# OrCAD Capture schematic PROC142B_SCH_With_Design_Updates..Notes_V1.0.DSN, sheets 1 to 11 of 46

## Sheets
1 17. SOC POWER SUPPLIES-DECAPS 2: size C; title: SOC POWER SUPPLIES - DECAPS 2; rev: B
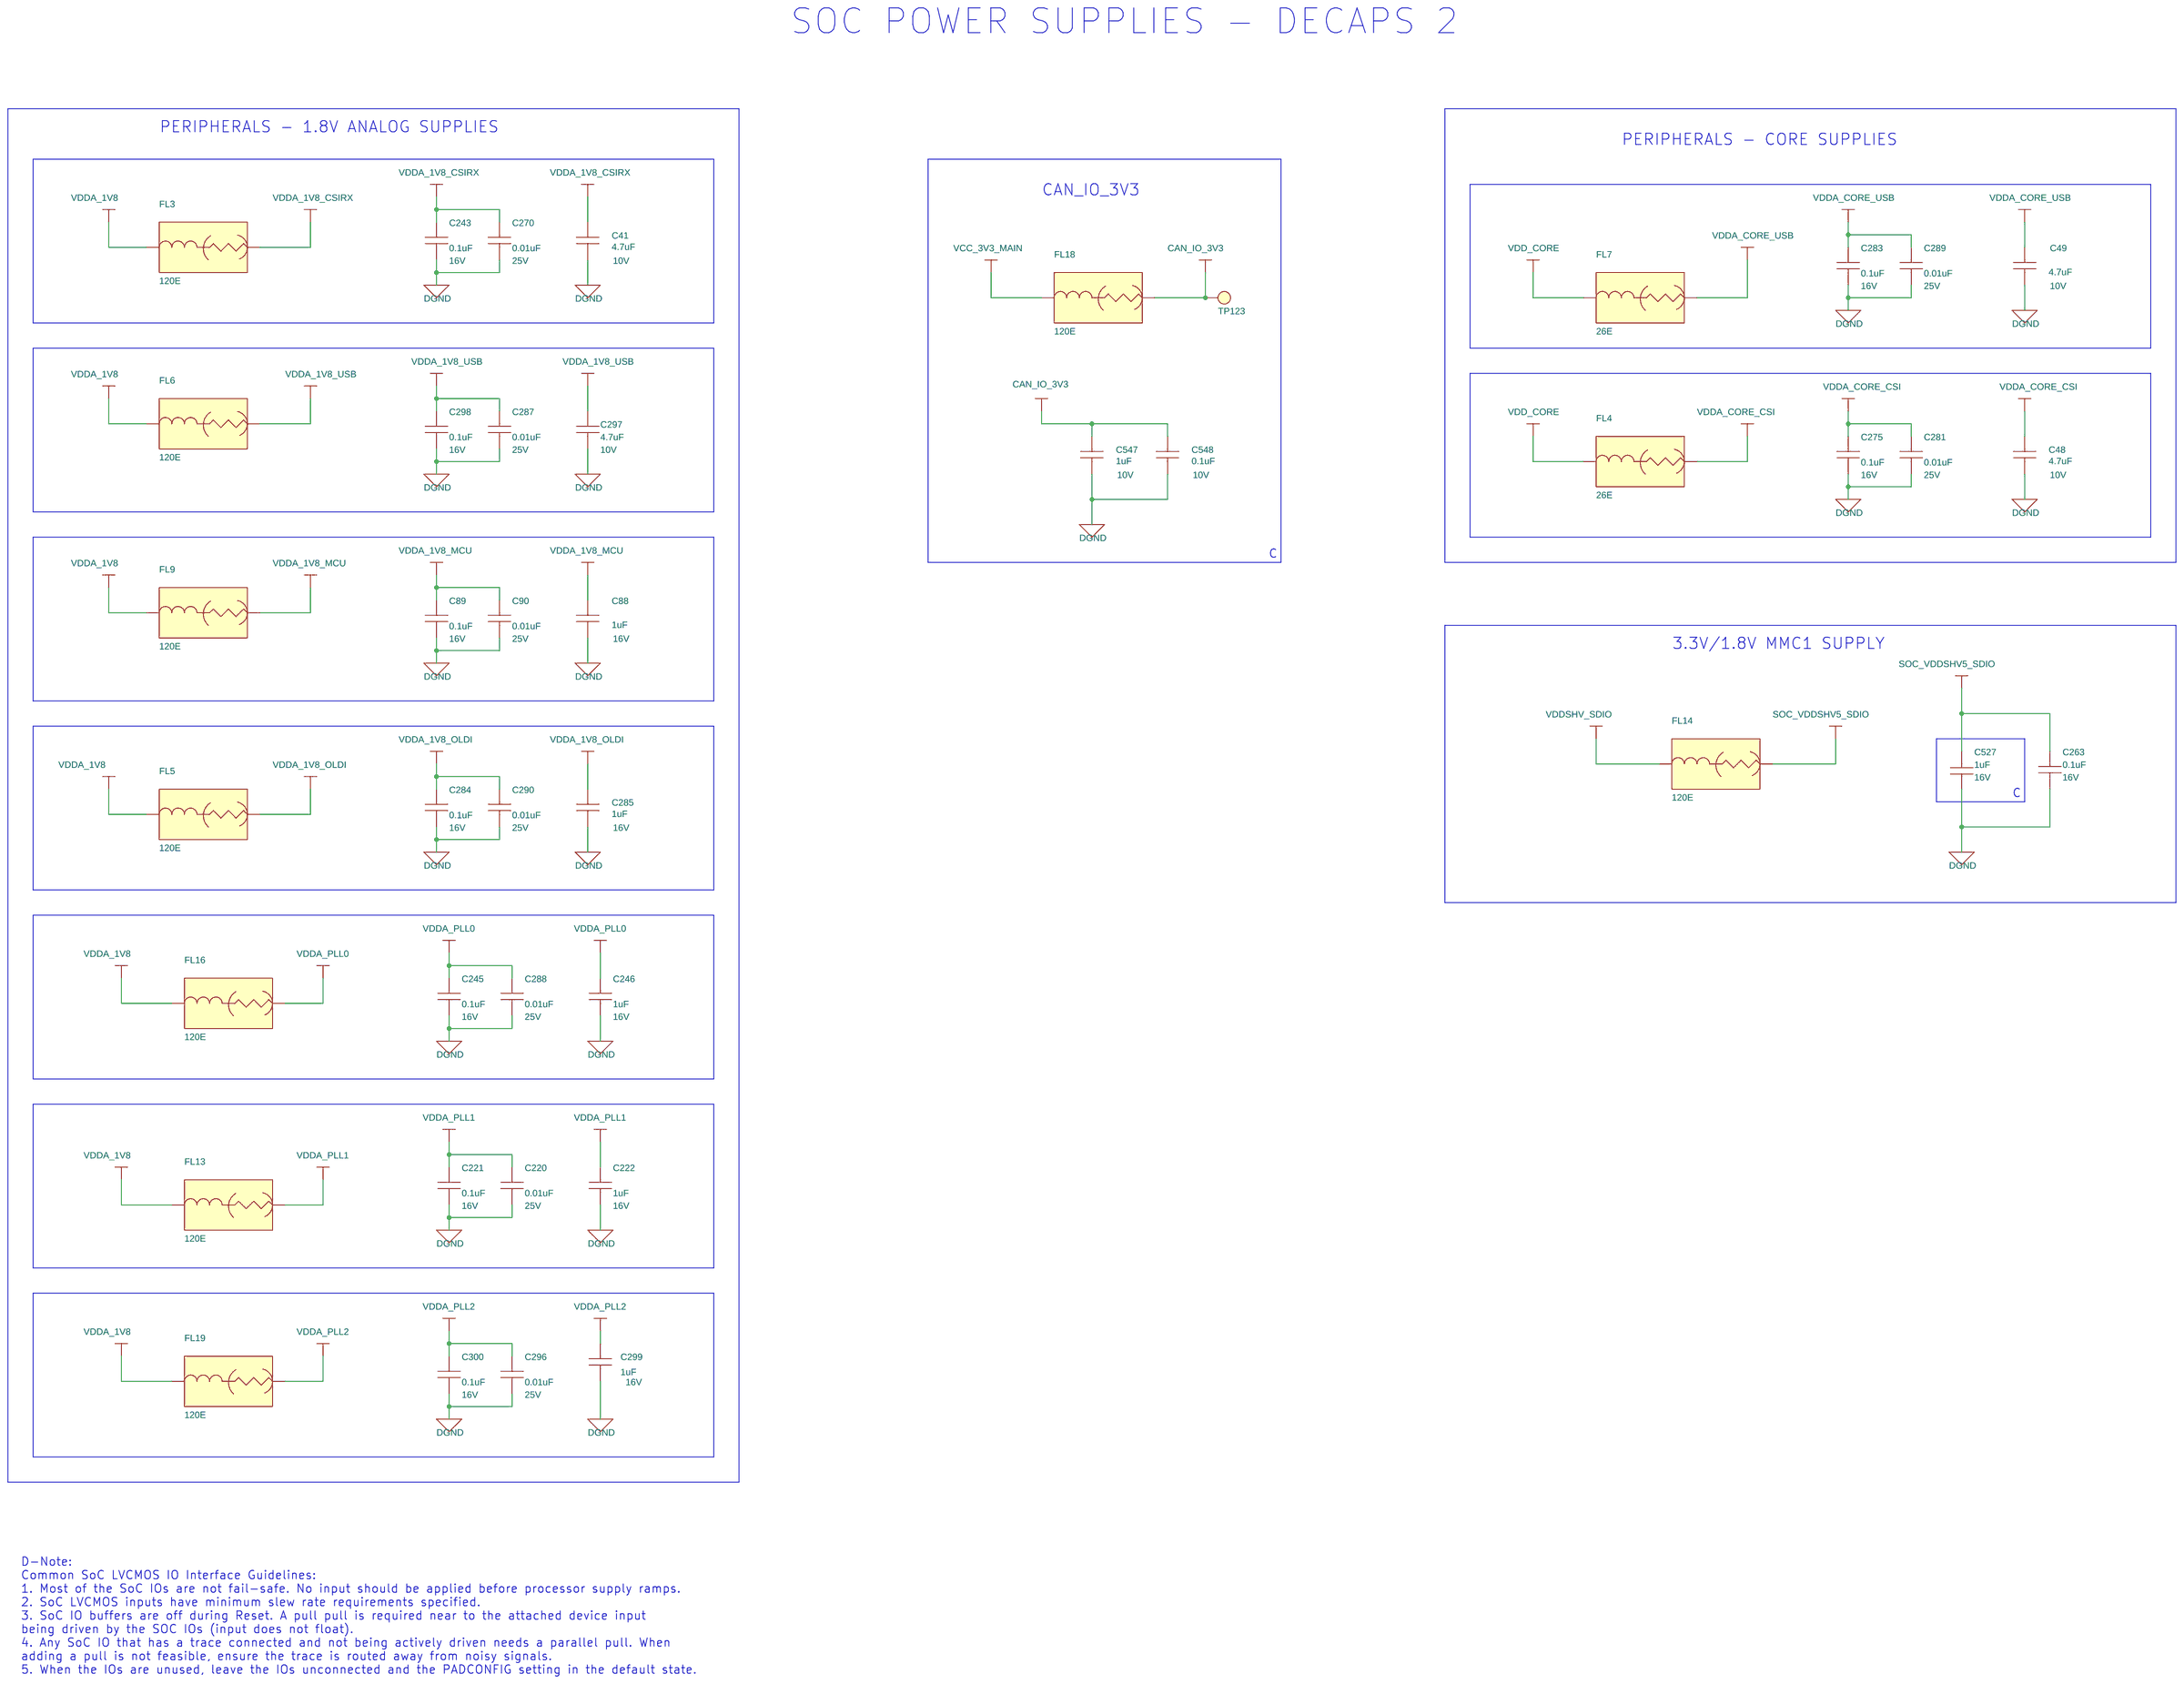
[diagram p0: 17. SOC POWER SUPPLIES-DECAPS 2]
2 03. LINKS TO KEY COLLATERAL&FAQ: title: LINKS TO KEY COLLATERALS AND FAQs
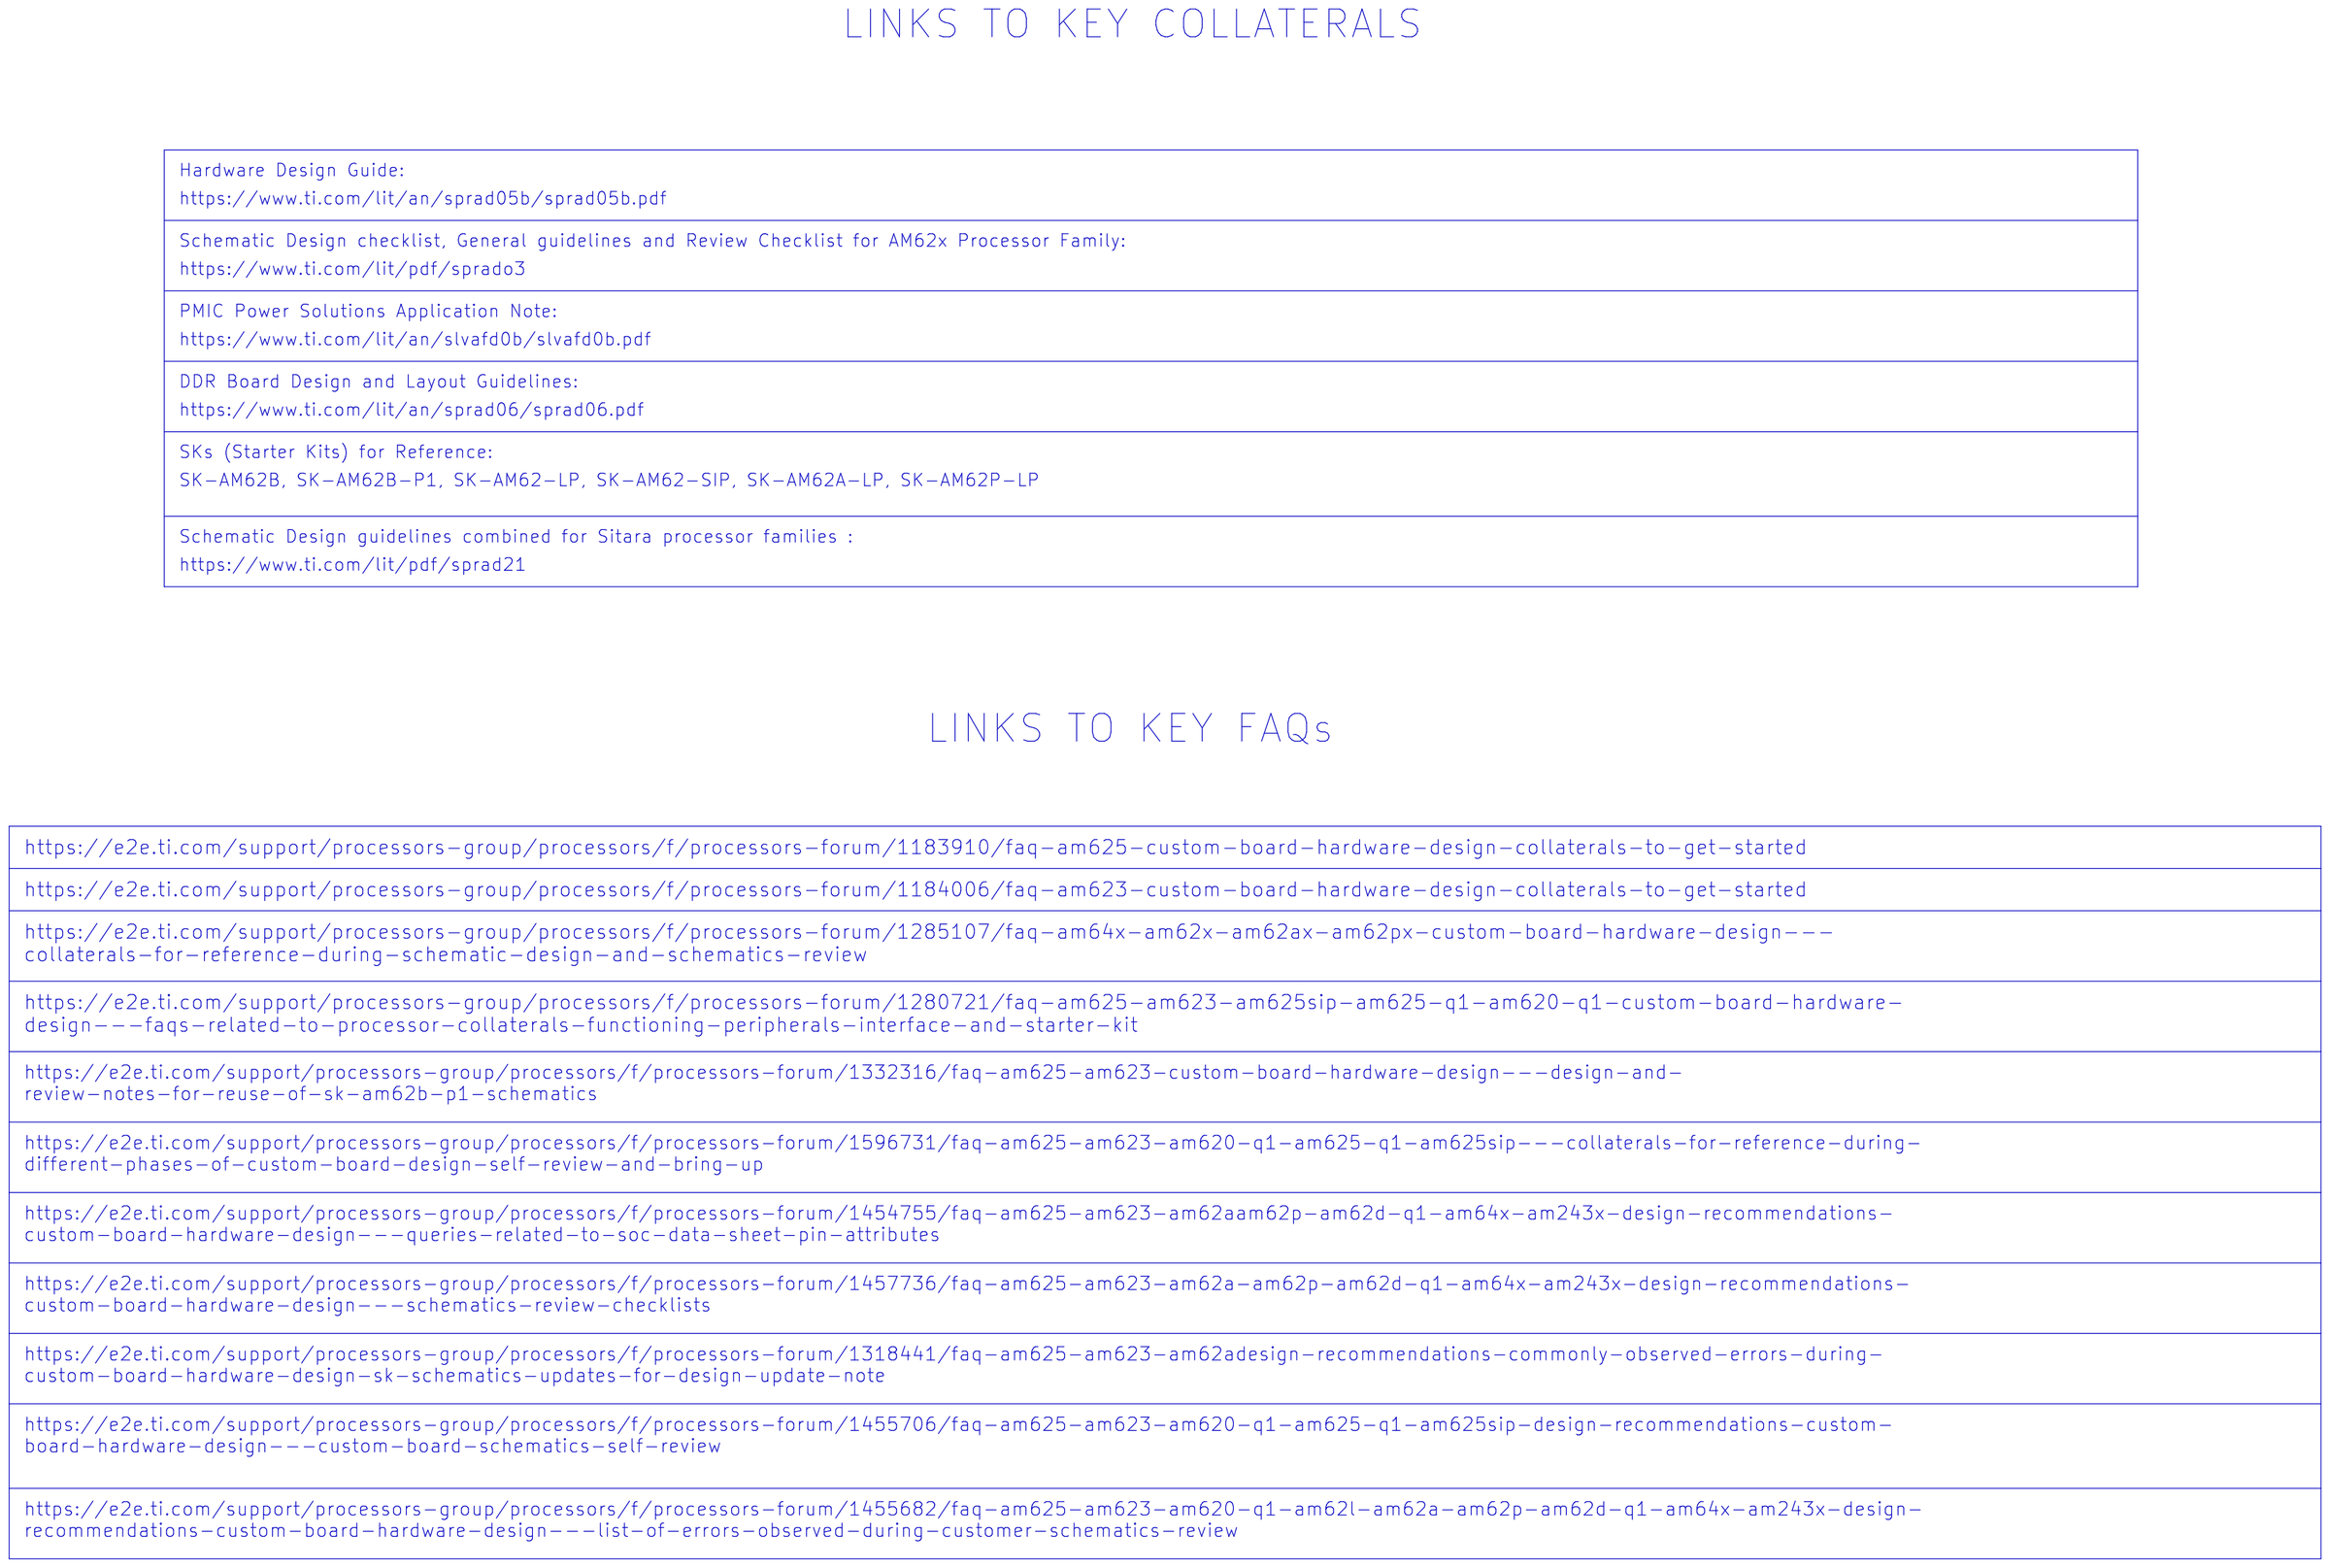
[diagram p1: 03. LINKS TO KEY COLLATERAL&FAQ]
3 30. AUTOMATION SIGNALS BUFFER: size C; title: AUTOMATION SIGNALS BUFFER
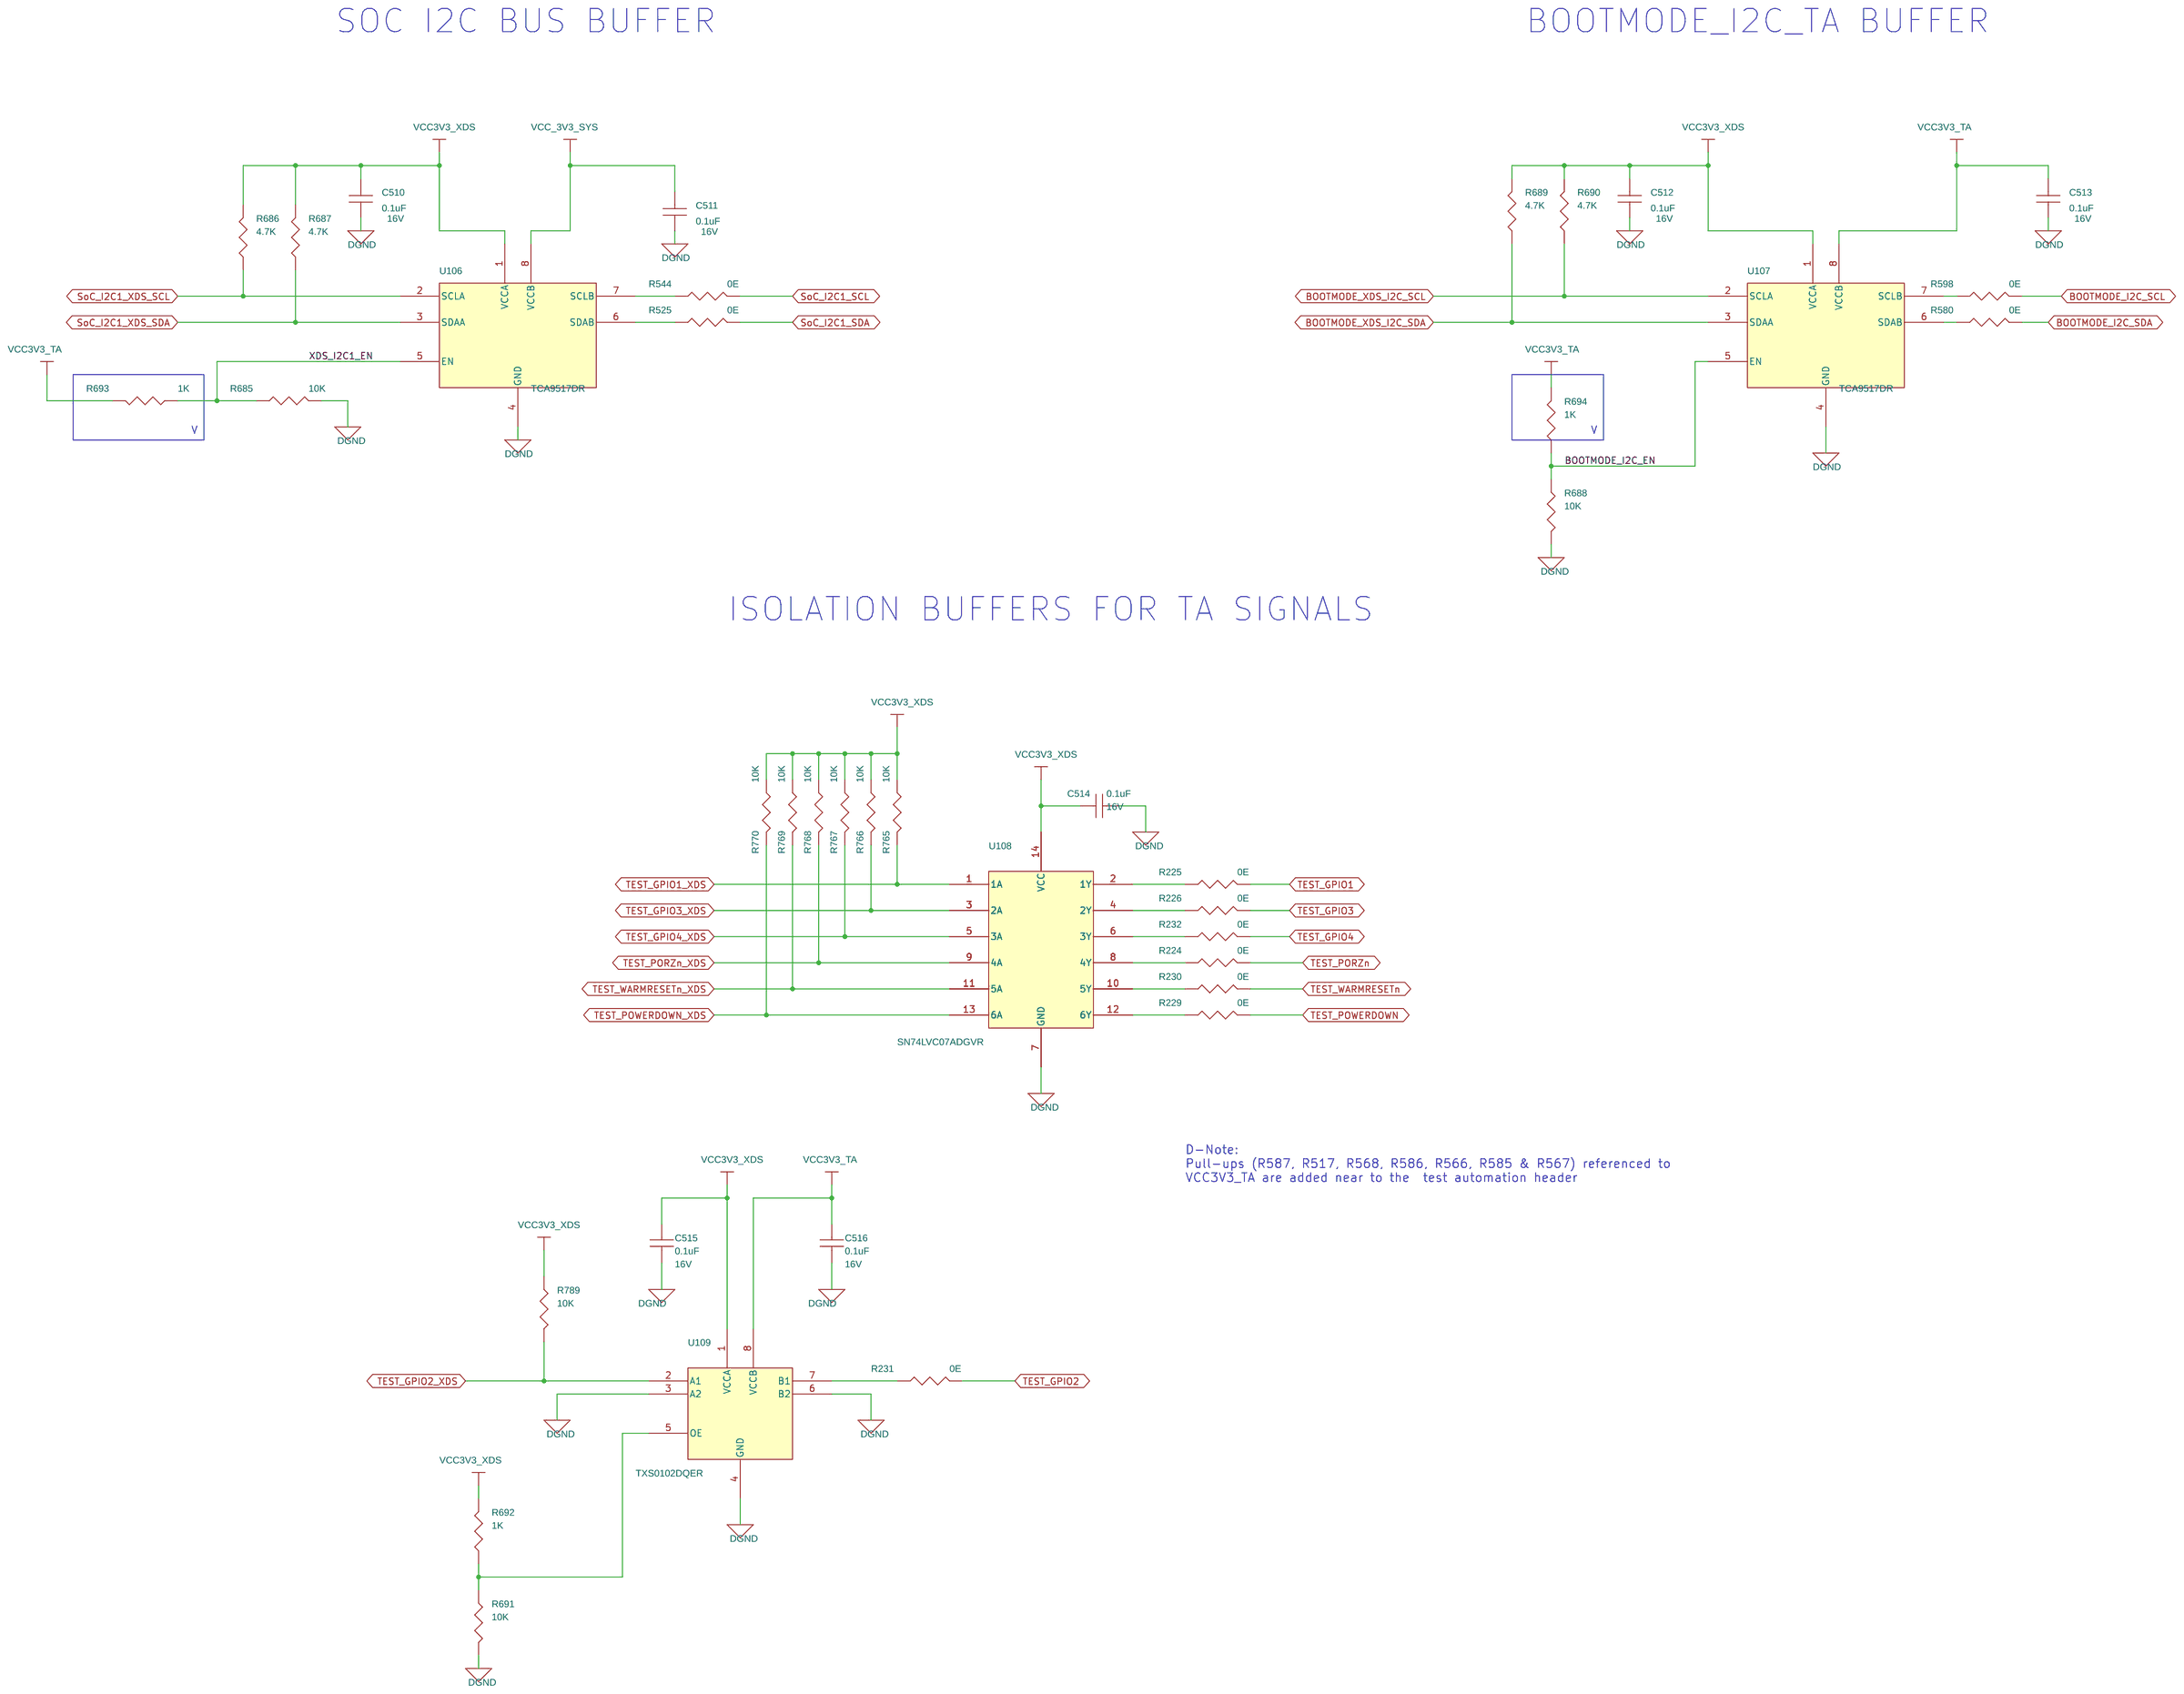
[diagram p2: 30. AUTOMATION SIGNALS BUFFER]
4 01. TABLE OF CONTENTS: title: TABLE OF CONTENTS
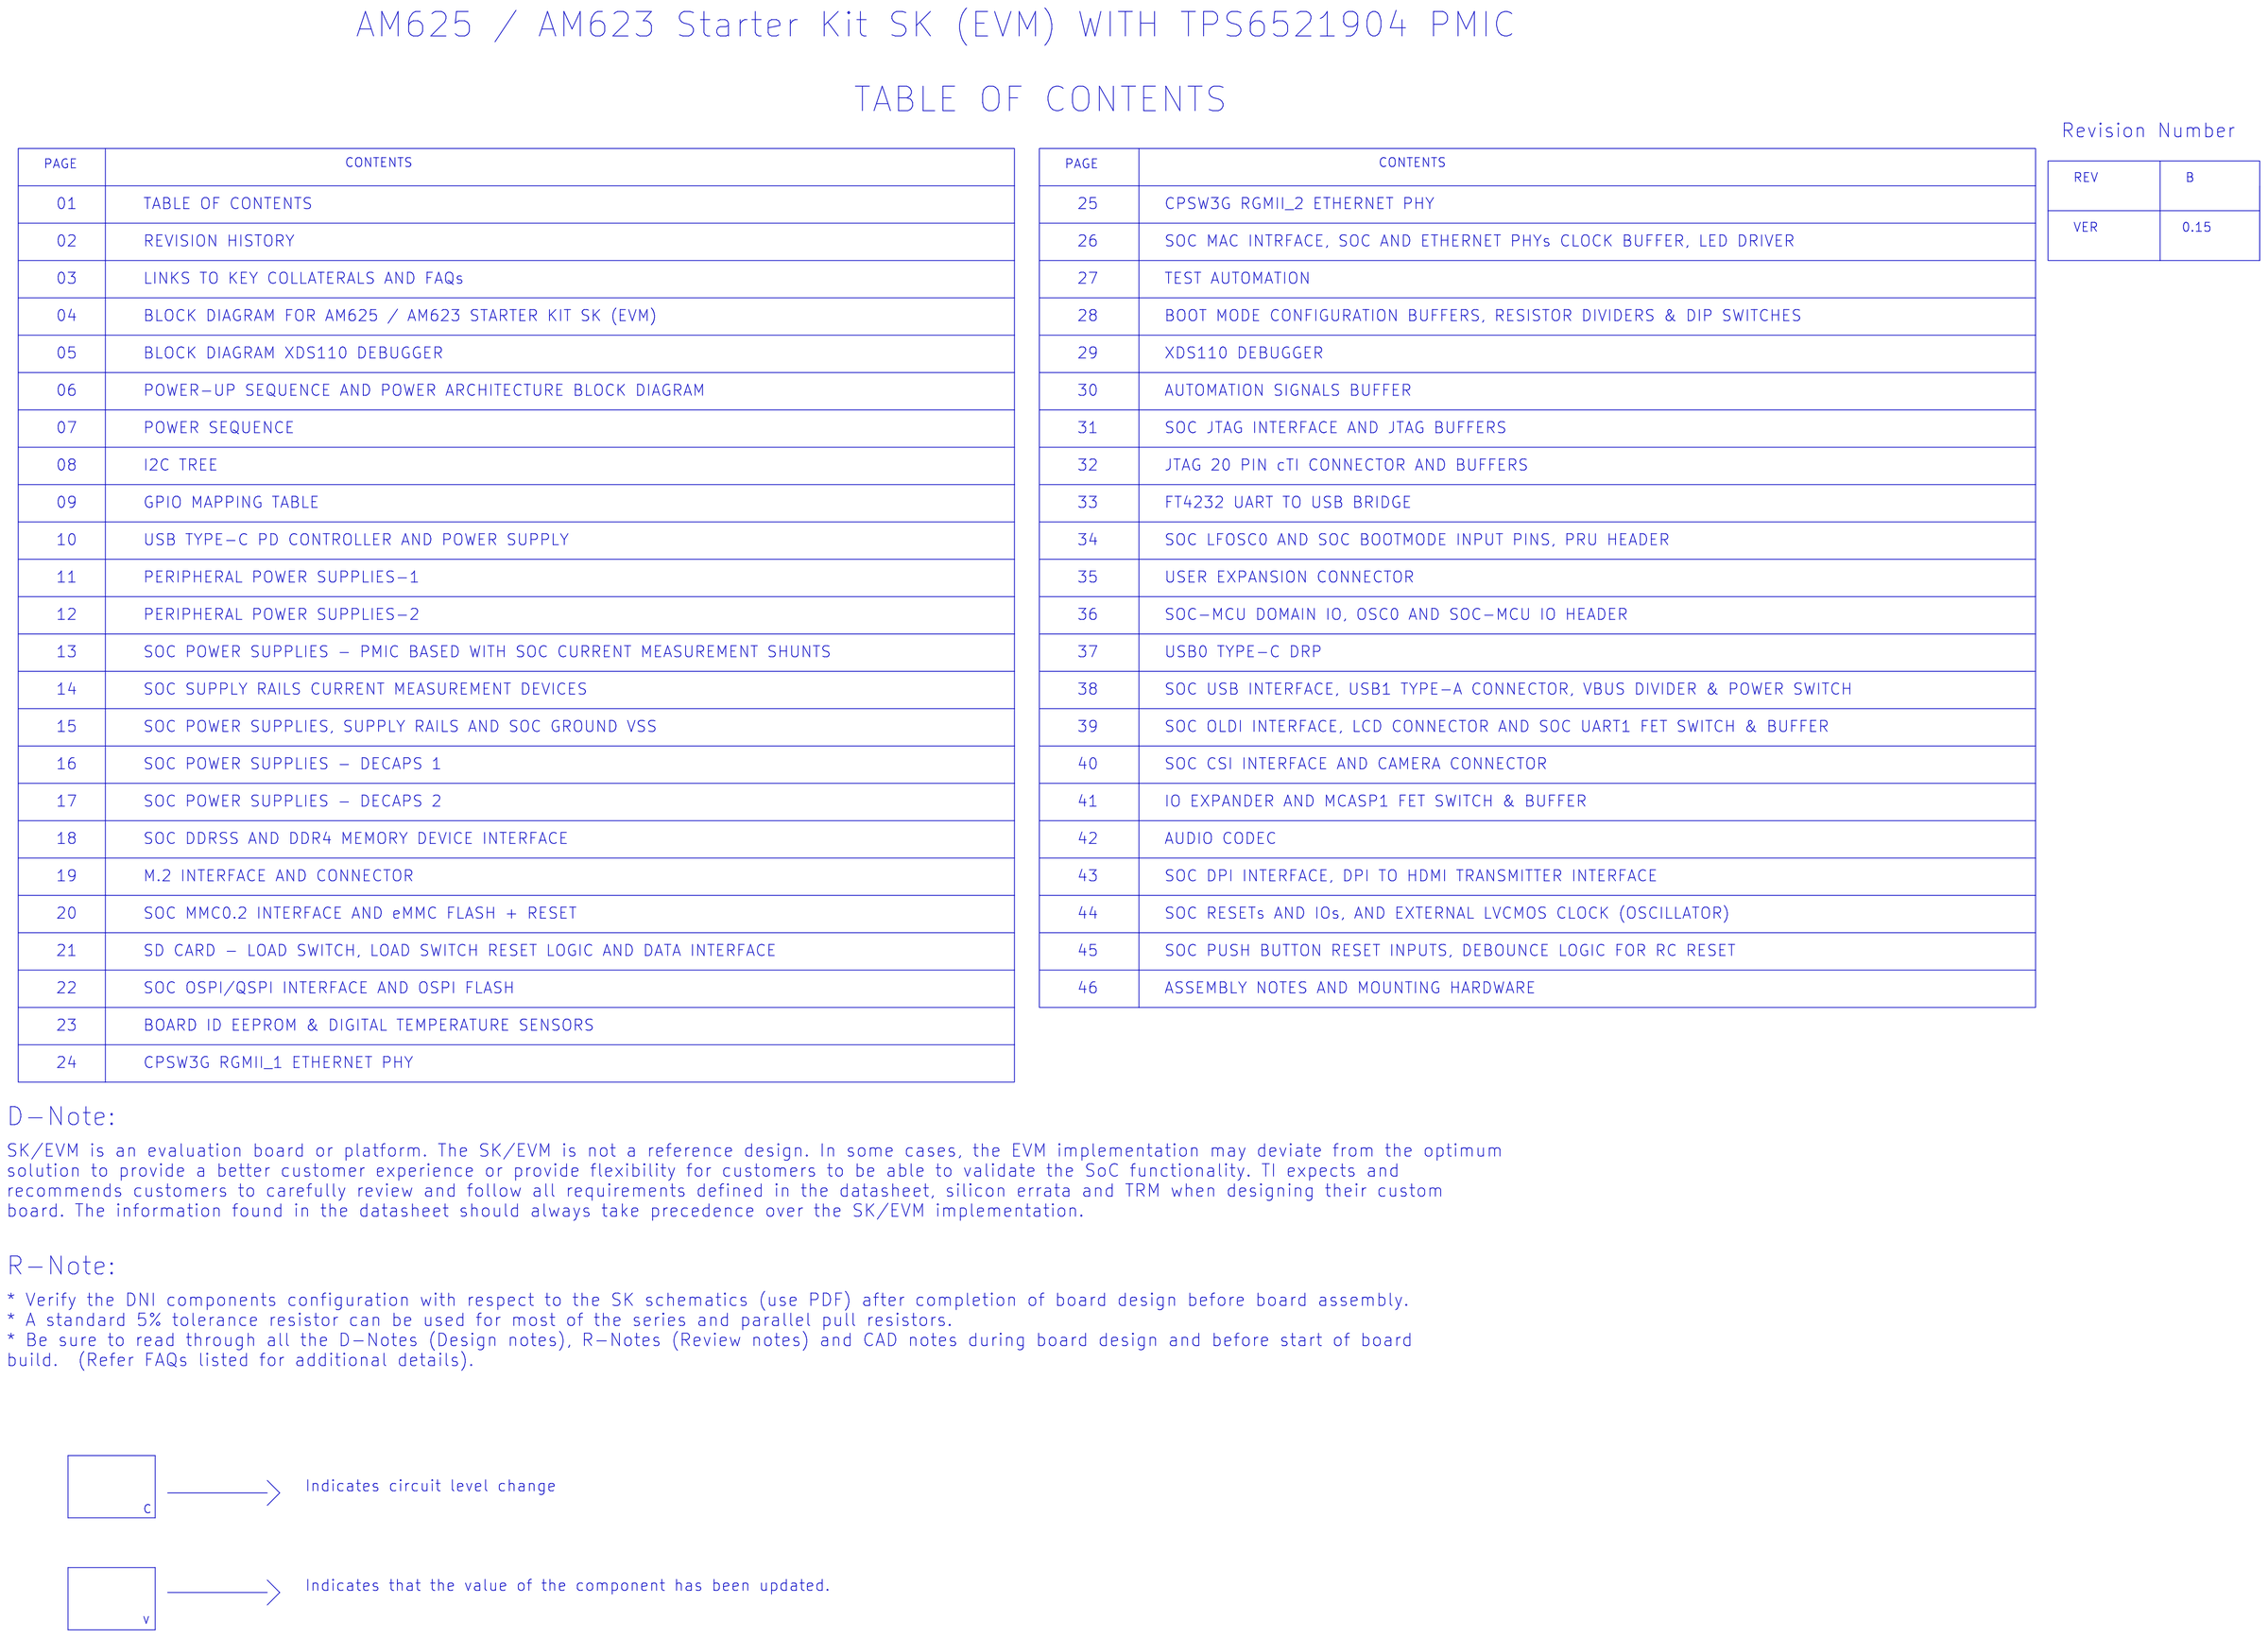
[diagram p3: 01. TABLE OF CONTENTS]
5 02. REVISION HISTORY: title: REVISION HISTORY
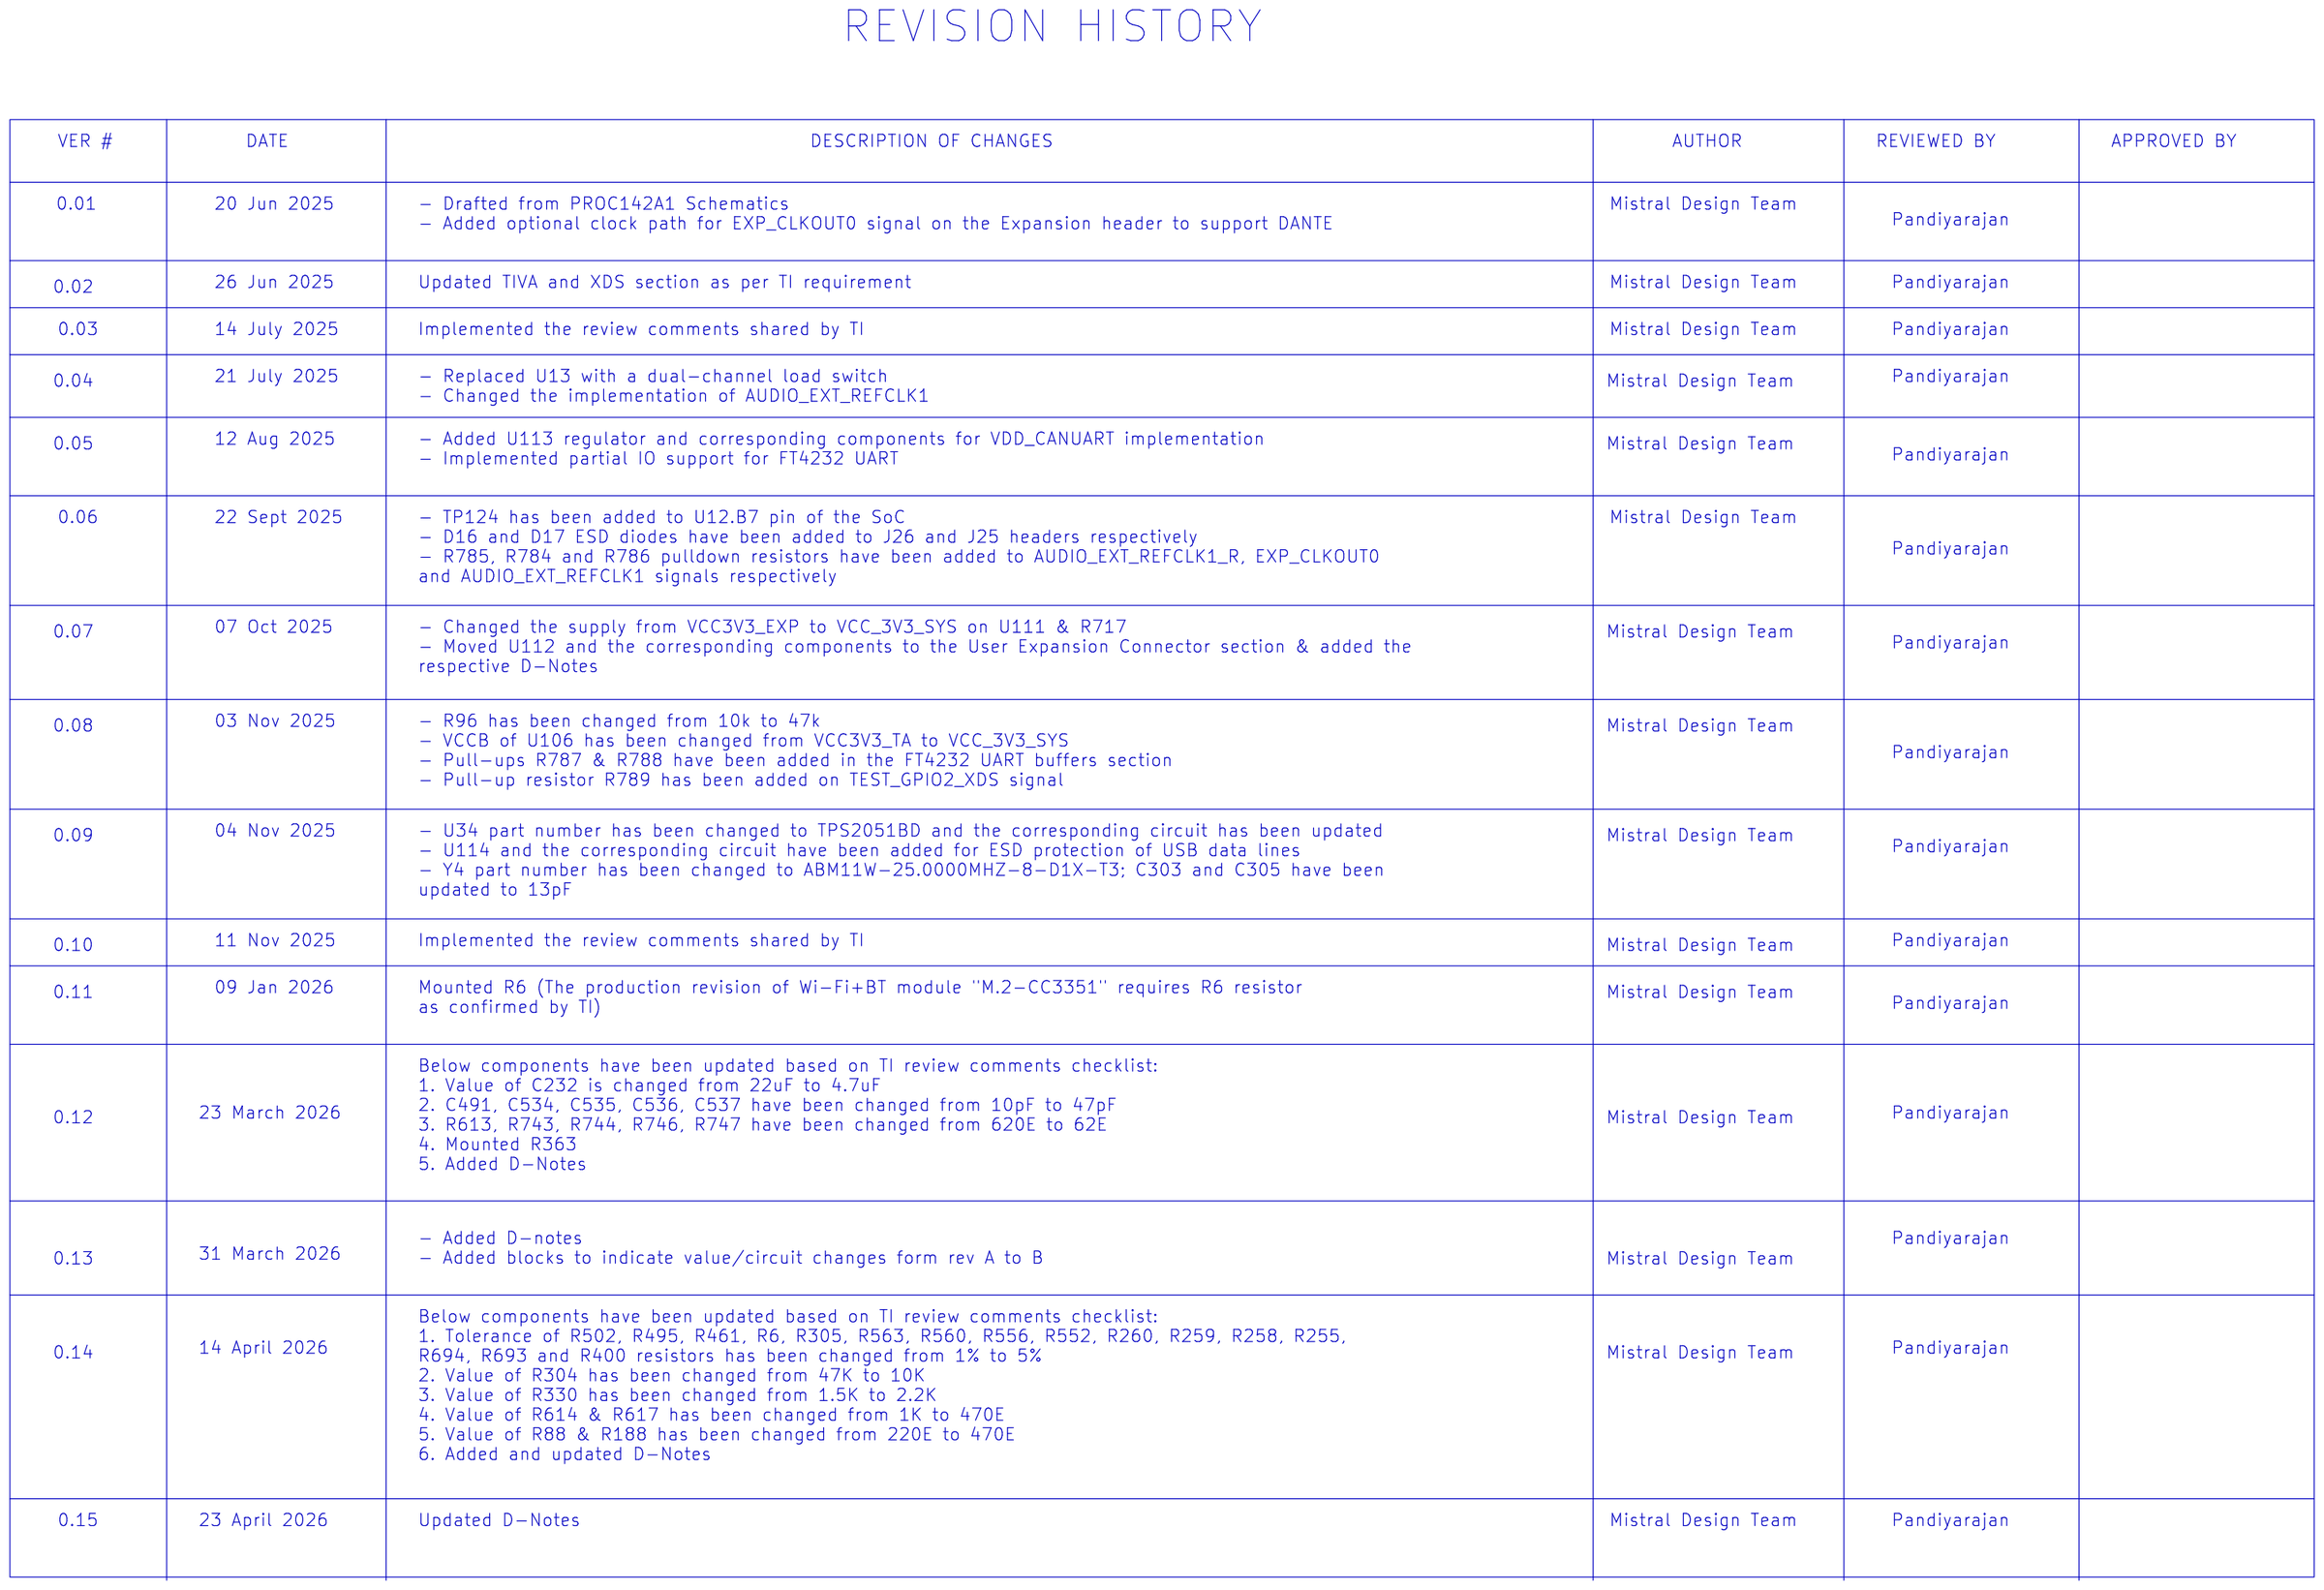
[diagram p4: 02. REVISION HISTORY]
6 04. BLOCK DIAGRAM AM62x_SKEVM: title: BLOCK DIAGRAM FOR AM625 / AM623 STARTER KIT SK (EVM)
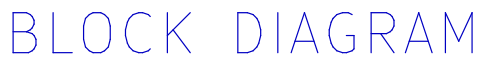
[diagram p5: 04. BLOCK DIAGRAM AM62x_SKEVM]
7 05. BLOCK DIAGRAM_XDS110: title: BLOCK DIAGRAM XDS110 DEBUGGER
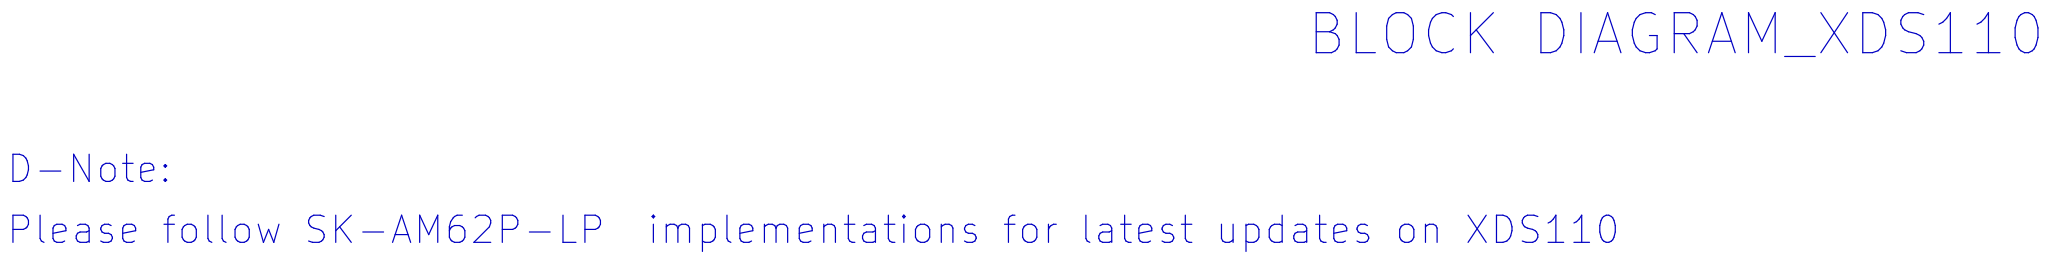
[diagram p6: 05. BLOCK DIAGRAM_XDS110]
8 06. POWER BLOCK DIAGRAM: title: POWER-UP SEQUENCE AND POWER ARCHITECTURE BLOCK DIAGRAM
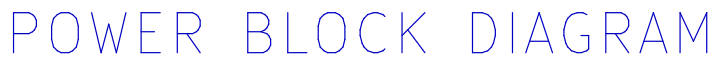
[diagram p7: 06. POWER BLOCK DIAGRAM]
9 07. POWER SEQUENCE: title: POWER SEQUENCE
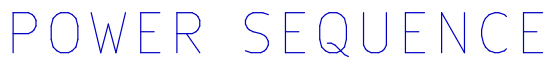
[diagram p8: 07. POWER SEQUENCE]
10 08. I2C TREE: title: I2C TREE
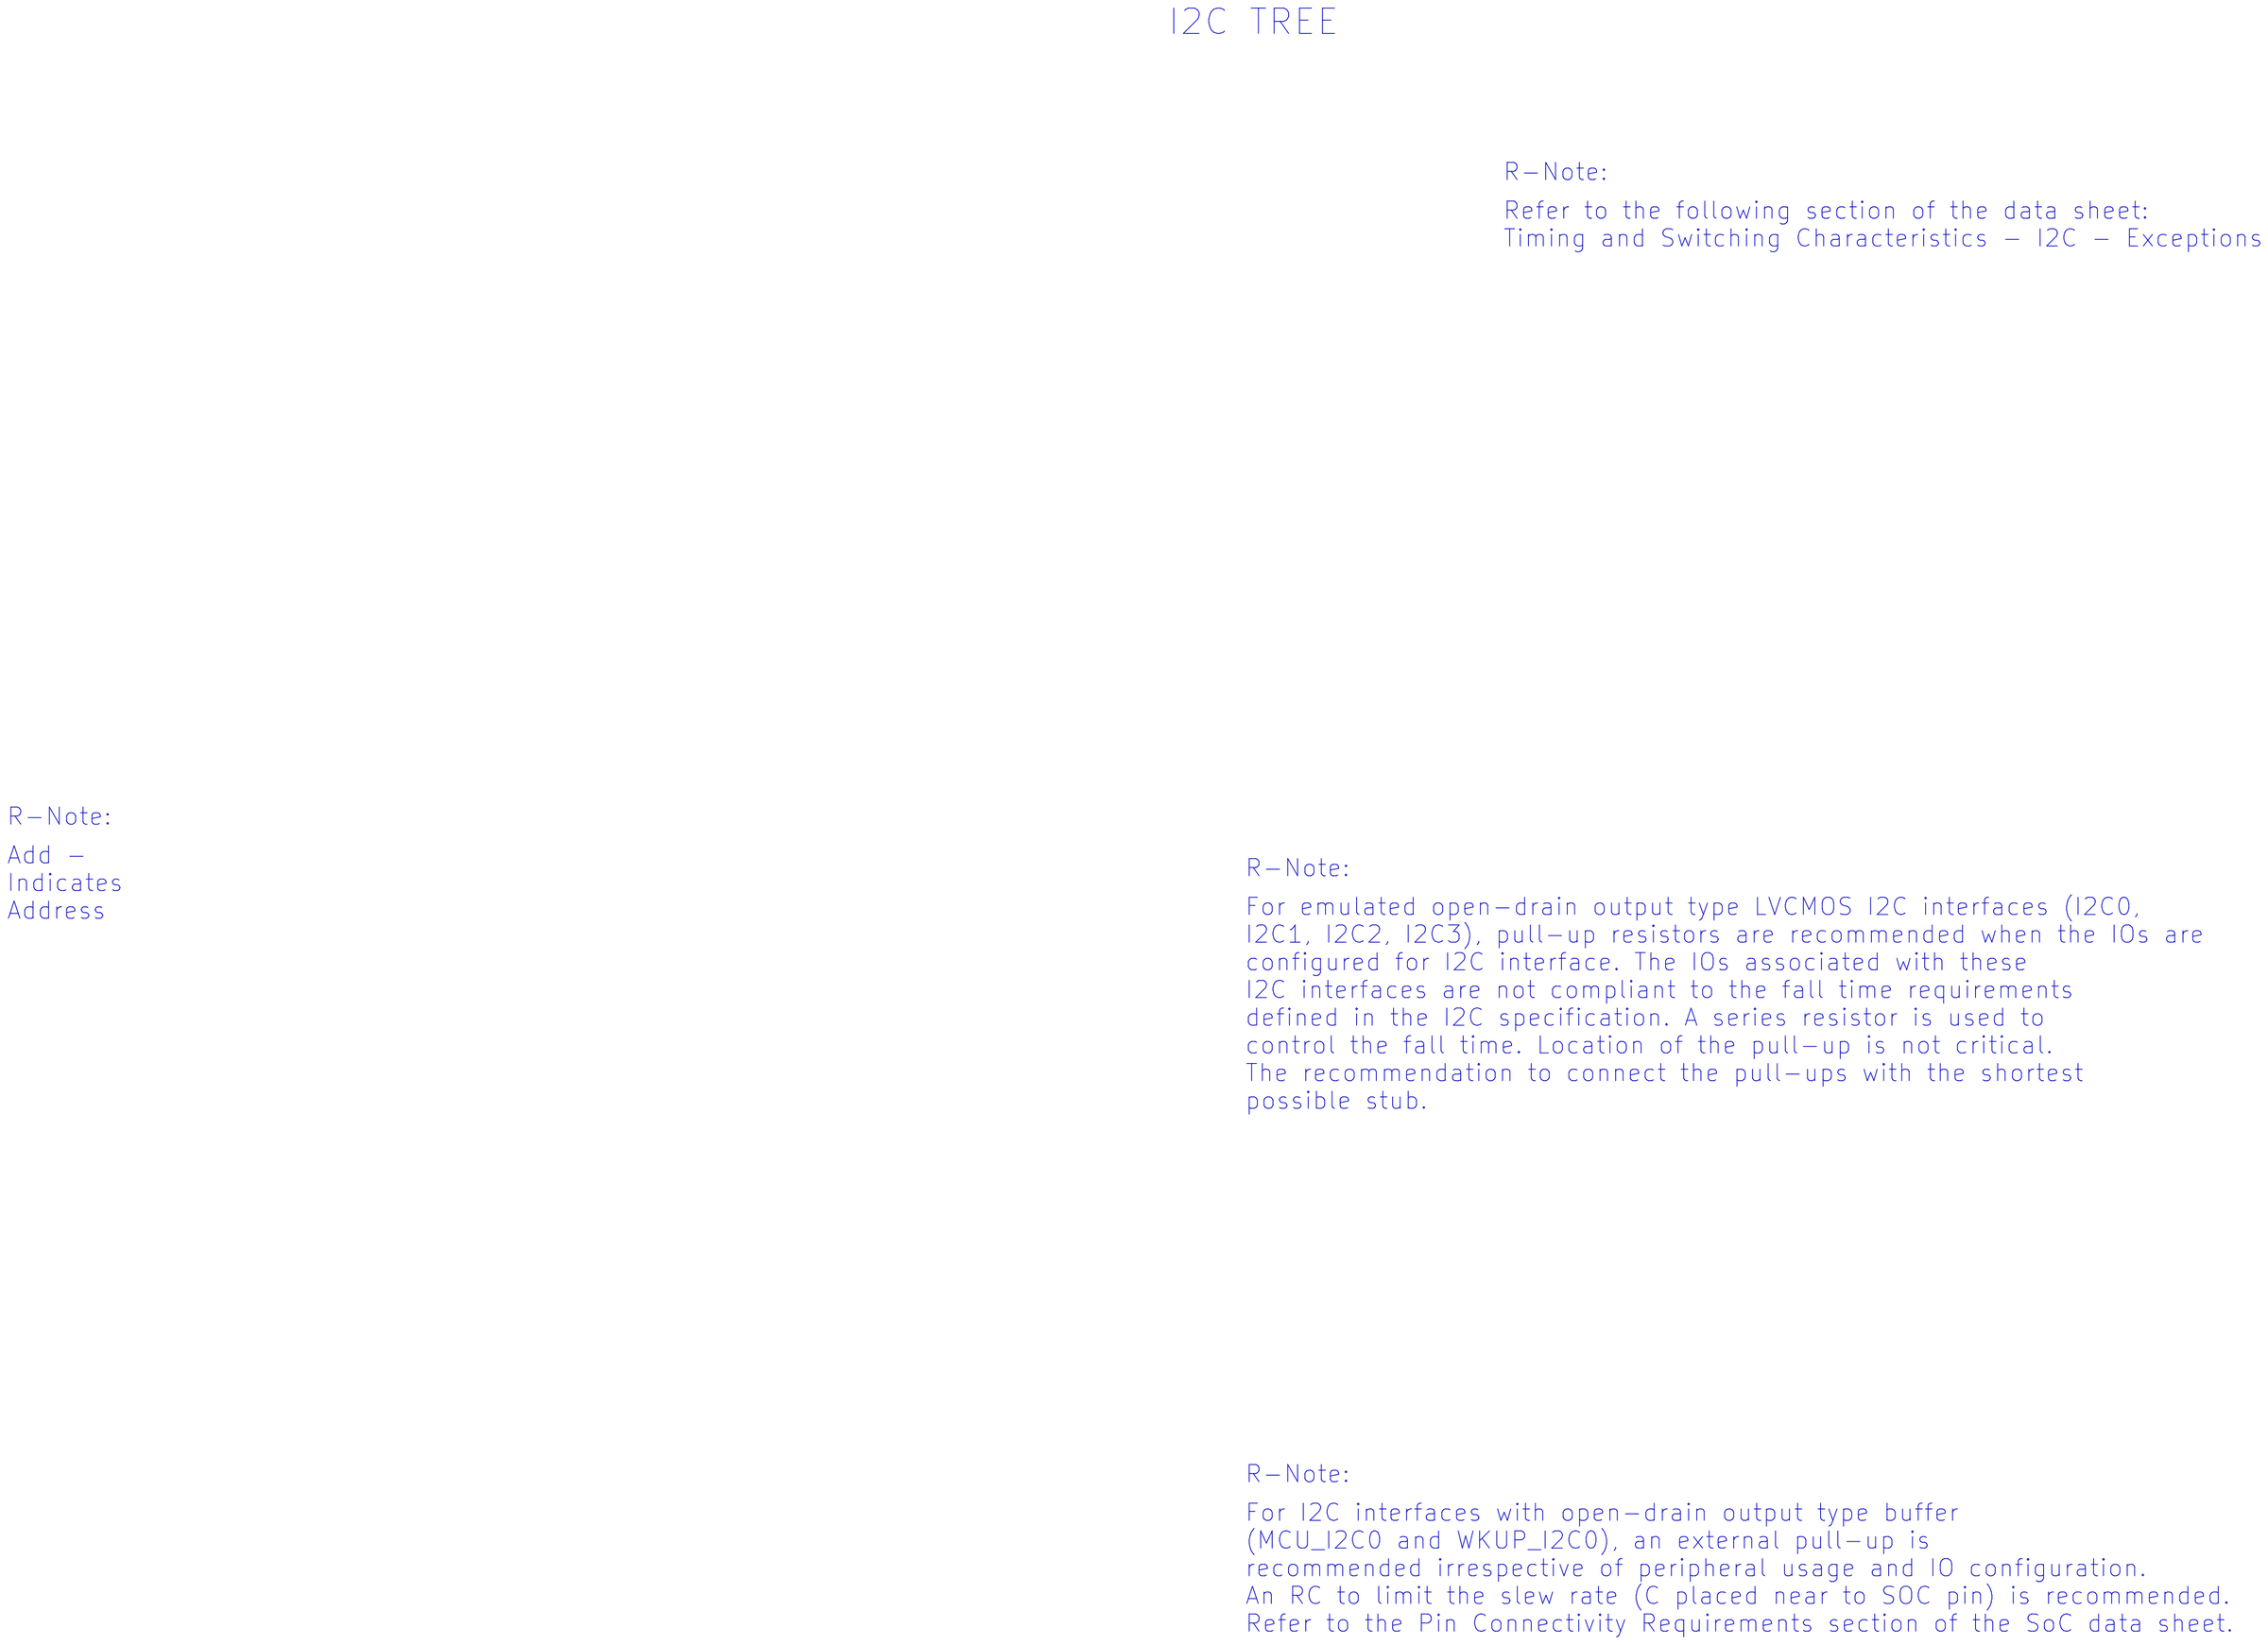
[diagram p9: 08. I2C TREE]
11 09. GPIO MAPPING TABLE: title: GPIO MAPPING TABLE
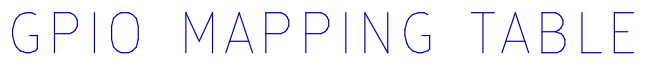
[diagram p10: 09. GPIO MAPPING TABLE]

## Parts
sheet 17. SOC POWER SUPPLIES-DECAPS 2
C41  4.7uF  [CAP0402_0-75]
C48  4.7uF  [CAP0402_0-75]
C49  4.7uF  [CAP0402_0-75]
C88  1uF  [CAP0201_0-5]
C89  0.1uF  [CAP0201_0-5]
C90  0.01uF  [CAP0201_0-5]
C220  0.01uF  [CAP0201_0-5]
C221  0.1uF  [CAP0201_0-5]
C222  1uF  [CAP0201_0-5]
C243  0.1uF  [CAP0201_0-5]
C245  0.1uF  [CAP0201_0-5]
C246  1uF  [CAP0201_0-5]
C263  0.1uF  [CAP0201_0-5]
C270  0.01uF  [CAP0201_0-5]
C275  0.1uF  [CAP0201_0-5]
C281  0.01uF  [CAP0201_0-5]
C283  0.1uF  [CAP0201_0-5]
C284  0.1uF  [CAP0201_0-5]
C285  1uF  [CAP0201_0-5]
C287  0.01uF  [CAP0201_0-5]
C288  0.01uF  [CAP0201_0-5]
C289  0.01uF  [CAP0201_0-5]
C290  0.01uF  [CAP0201_0-5]
C296  0.01uF  [CAP0201_0-5]
C297  4.7uF  [CAP0402_0-75]
C298  0.1uF  [CAP0201_0-5]
C299  1uF  [CAP0201_0-5]
C300  0.1uF  [CAP0201_0-5]
C527  1uF  [CAP0201_0-5]
C547  1uF  [CAP0201_0-5]
C548  0.1uF  [CAP0201_0-5]
FL3  120E  [EMIFIL_BLM15A_0402_0-6]
FL4  26E  [EMIFIL_BLM18K_0603_0-7]
FL5  120E  [EMIFIL_BLM15A_0402_0-6]
FL6  120E  [EMIFIL_BLM15A_0402_0-6]
FL7  26E  [EMIFIL_BLM18K_0603_0-7]
FL9  120E  [EMIFIL_BLM15A_0402_0-6]
FL13  120E  [EMIFIL_BLM15A_0402_0-6]
FL14  120E  [EMIFIL_BLM15A_0402_0-6]
FL16  120E  [EMIFIL_BLM15A_0402_0-6]
FL18  120E  [EMIFIL_BLM15A_0402_0-6]
FL19  120E  [EMIFIL_BLM15A_0402_0-6]
TP123  TP20_SMD  [TP20_SMD]
sheet 30. AUTOMATION SIGNALS BUFFER
C510  0.1uF  [CAP0201_0-5]
C511  0.1uF  [CAP0201_0-5]
C512  0.1uF  [CAP0201_0-5]
C513  0.1uF  [CAP0201_0-5]
C514  0.1uF  [CAP0201_0-5]
C515  0.1uF  [CAP0201_0-5]
C516  0.1uF  [CAP0201_0-5]
R224  0E  [RES0201_0-5]
R225  0E  [RES0201_0-5]
R226  0E  [RES0201_0-5]
R229  0E  [RES0201_0-5]
R230  0E  [RES0201_0-5]
R231  0E  [RES0201_0-5]
R232  0E  [RES0201_0-5]
R525  0E  [RES0402_0-5]
R544  0E  [RES0402_0-5]
R580  0E  [RES0402_0-5]
R598  0E  [RES0402_0-5]
R685  10K  [RES0201_0-5]
R686  4.7K  [RES0201_0-5]
R687  4.7K  [RES0201_0-5]
R688  10K  [RES0201_0-5]
R689  4.7K  [RES0201_0-5]
R690  4.7K  [RES0201_0-5]
R691  10K  [RES0201_0-5]
R692  1K  [RES0402_0-5]
R693  1K  [RES0402_0-5]
R694  1K  [RES0402_0-5]
R765  10K  [RES0201_0-5]
R766  10K  [RES0201_0-5]
R767  10K  [RES0201_0-5]
R768  10K  [RES0201_0-5]
R769  10K  [RES0201_0-5]
R770  10K  [RES0201_0-5]
R789  10K  [RES0201_0-5]
U106  TCA9517DR  [SOIC8_1-8]
U107  TCA9517DR  [SOIC8_1-8]
U108  SN74LVC07ADGVR  [TVSOP14_15-74_180X150_1-2]
U109  TXS0102DQER  [X2SON8_TXS0102_40X60_0-4]

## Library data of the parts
C41 C48 C49 C297 = CAP: CAP CERAMIC 4.7uF 10V 20% X5R 0402; Chkd/date: MANIRAJA/110718; Crtd /date: ALVY/110718; Custom_Duty: 15%; Customs_HS_Code: 85322990; Distributor_name: DIGIKEY; Distributor_part_number: 490-14306-1-ND; Footprint Path: Y:\MIS_DATABASE\Library\ALTIUM_TOOL\PCB_FOOTPRINTS\Altium_Footprint_Lib.PcbLib; Height: 0.65MM; Library Path: Y:\MIS_DATABASE\Library\ALTIUM_TOOL\SCHEMATICS_PARTS\MS_DISCRETE_Library.schlib; Mfr_name: MURATA; Mfr_part_number: GRM155R61A475MEAAD; Mistral Part No: 120012060002-R; Package: 0402; Part_type: CAPACITORS\CERAMIC; Project: TI_J7SVB_PCIE_ADD-ON-CARD; RoHS: RoHS; Temperature: -55°C+85°C; Tolerance: 20%; Voltage: 10V; Wattage: NA; Weight: 14mg; Datasheet: Y:\MIS_DATABASE\DATASHEETS\CAPACITORS\GRM155R61A475MEAAD.PDF
C88 C222 C246 C285 C299 C527 = CAP: CAP CERAMIC 1uF 16V 20% X5R 0201; Chkd/date: MANIRAJA/300520; Crtd /date: ALVY/260520; Custom_Duty: 15%; Customs_HS_Code: 85322990; Distributor_name: DIGIKEY; Distributor_part_number: 490-18654-1-ND; Footprint Path: Y:\MIS_DATABASE\Library\ALTIUM_TOOL\PCB_FOOTPRINTS\Altium_Footprint_Lib.PcbLib; Height: 0.39MM; Library Path: Y:\MIS_DATABASE\Library\ALTIUM_TOOL\SCHEMATICS_PARTS\MS_DISCRETE_Library.schlib; Mfr_name: MURATA; Mfr_part_number: GRM033R61C105ME15D; Mistral Part No: 120018090038-R; Package: 0201; Part_type: CAPACITORS\CERAMIC; Project: QCS610_NANOSOM; RoHS: RoHS; Temperature: -55°C+85°C; Tolerance: 20%; Voltage: 16V; Wattage: NA; Weight: 0.33mg; Datasheet: Y:\MIS_DATABASE\DATASHEETS\CAPACITORS\GRM033R61C105ME15.PDF
C89 C221 C243 C245 C263 C275 C283 C284 C298 C300 = CAP: CAP CERAMIC 0.1uF 16V 10% X5R 0201; Chkd/date: MANIRAJA/230118; Crtd /date: MANIRAJA/230118; Custom_Duty: 15%; Customs_HS_Code: 85322990; Distributor_name: DIGIKEY; Distributor_part_number: 490-14305-1-ND; Footprint Path: Y:\MIS_DATABASE\Library\ALTIUM_TOOL\PCB_FOOTPRINTS\Altium_Footprint_Lib.PcbLib; Height: 0.33MM; Library Path: Y:\MIS_DATABASE\Library\ALTIUM_TOOL\SCHEMATICS_PARTS\MS_DISCRETE_Library.schlib; Mfr_name: MURATA; Mfr_part_number: GRM033R61C104KE14D; Mistral Part No: 120009030072-R; Package: 0201; Part_type: CAPACITORS\CERAMIC; Project: TI_MAXIE_CPB; RoHS: RoHS; Temperature: -55°C+85°C; Tolerance: 10%; Voltage: 16V; Wattage: NA; Weight: 0.33mg; Datasheet: Y:\MIS_DATABASE\DATASHEETS\CAPACITORS\GRM033R61C104KE14.PDF
C90 C220 C270 C281 C287-C290 C296 = CAP: CAP CERAMIC 0.01uF 25V 10% X5R 0201; Chkd/date: MANIRAJA/230118; Crtd /date: MANIRAJA/230118; Custom_Duty: 15%; Customs_HS_Code: 85322990; Distributor_name: DIGIKEY; Distributor_part_number: GRM033R61E103KA12J-ND; Footprint Path: Y:\MIS_DATABASE\Library\ALTIUM_TOOL\PCB_FOOTPRINTS\Altium_Footprint_Lib.PcbLib; Height: 0.33MM; Library Path: Y:\MIS_DATABASE\Library\ALTIUM_TOOL\SCHEMATICS_PARTS\MS_DISCRETE_Library.schlib; Mfr_name: MURATA; Mfr_part_number: GRM033R61E103KA12J; Mistral Part No: 120018010007-R; Package: 0201; Part_type: CAPACITORS\CERAMIC; Project: TI_MAXIE_CPB; RoHS: RoHS; Temperature: -55°C+85°C; Tolerance: 10%; Voltage: 25V; Wattage: NA; Weight: 0.33mg; Datasheet: Y:\MIS_DATABASE\DATASHEETS\CAPACITORS\GRM033R61E103KA12.PDF
C547 = CAP: CAP CERAMIC 1uF 10V 20% X5R 0201; Chkd/date: NAVEED/070415; Crtd /date: VASANTHA/230314; Custom_Duty: 15%; Customs_HS_Code: 85322990; Distributor_name: DIGIKEY; Distributor_part_number: 1276-1324-1-ND; Footprint Path: Y:\MIS_DATABASE\Library\ALTIUM_TOOL\PCB_FOOTPRINTS\Altium_Footprint_Lib.PcbLib; Height: 0.35MM; Library Path: Y:\MIS_DATABASE\Library\ALTIUM_TOOL\SCHEMATICS_PARTS\MS_DISCRETE_Library.schlib; Mfr_name: SAMSUNG; Mfr_part_number: CL03A105MP3NSNC; Mistral Part No: 120015030003-R; Package: 0201; Part_type: CAPACITORS\CERAMIC; Project: DUET BOARDS; RoHS: RoHS; Temperature: -55°C+85°C; Tolerance: 20%; Voltage: 10V; Wattage: NA; Weight: 0.17mg; Datasheet: Y:\MIS_DATABASE\DATASHEETS\CAPACITORS\CL03A105MP3NSNC.PDF
C548 = CAP: CAP CERAMIC 0.1uF 10V 10% X5R 0201; Chkd/date: MANIRAJA/290421; Crtd /date: ALVY/290421; Custom_Duty: 15%; Customs_HS_Code: 85322990; Distributor_name: DIGIKEY; Distributor_part_number: 1276-1115-1-ND; Footprint Path: Y:\MIS_DATABASE\Library\ALTIUM_TOOL\PCB_FOOTPRINTS\Altium_Footprint_Lib.PcbLib; Height: 0.33MM; Library Path: Y:\MIS_DATABASE\Library\ALTIUM_TOOL\SCHEMATICS_PARTS\MS_DISCRETE_Library.schlib; Mfr_name: SAMSUNG; Mfr_part_number: CL03A104KP3NNNC; Mistral Part No: 120009050017-R; Package: 0201; Part_type: CAPACITORS\CERAMIC; Project: SRMS-SAR_BRD; RoHS: RoHS; Temperature: -55°C+85°C; Tolerance: 10%; Voltage: 10V; Wattage: NA; Weight: 0.33mg; Datasheet: Y:\MIS_DATABASE\DATASHEETS\CAPACITORS\CL03A104KP3NNNC.PDF
FL3 FL5 FL6 FL9 FL13 FL14 FL16 FL18 FL19 = EMIFILTER_IND: IND FERRITE BEAD CHIP 120E 2A 0402; Chkd/date: NAVEED/241114; Crtd /date: USMAN/170613; Custom_Duty: 24%; Customs_HS_Code: 85369090; Distributor_name: DIGIKEY; Distributor_part_number: 490-9656-1-ND; Footprint Path: Y:\MIS_DATABASE\Library\ALTIUM_TOOL\PCB_FOOTPRINTS\Altium_Footprint_Lib.PcbLib; Height: 0.55MM; Library Path: Y:\MIS_DATABASE\Library\ALTIUM_TOOL\SCHEMATICS_PARTS\MS_FILTER_Library.schlib; Mfr_name: MURATA; Mfr_part_number: BLM15PX121SN1D; Mistral Part No: 130013060022-R; Package: 0402; Part_type: INDUCTOR; Project: GEN_3-8; RoHS: RoHS; Temperature: -55°C+125°C; Tolerance: 25%; Voltage: NA; Wattage: NA; Weight: 1mg; Datasheet: Y:\MIS_DATABASE\DATASHEETS\DISCRETES\INDUCTORS\BLM15-SN1-SER.PDF
FL4 FL7 = EMIFILTER_IND: FERRITE CHIP 26E 6A 0603; Chkd/date: NAVEED/190115; Crtd /date: USMAN/251013; Custom_Duty: 15%; Customs_HS_Code: 85412900; Distributor_name: DIGIKEY; Distributor_part_number: 490-3995-1-ND; Height: 0.65MM; Mfr_name: MURATA; Mfr_part_number: BLM18SG260TN1D; Mistral Part No: 130013100028-R; Package: 0603; Part_type: FILTER; Project: DTRM_SBAND; RoHS: RoHS; Temperature: -55°C+125°C; Tolerance: 25%; Voltage: NA; Wattage: NA; Weight: 2mg; Datasheet: Y:\MIS_DATABASE\DATASHEETS\DISCRETES\INDUCTORS\BLM18K-SERIES.PDF
TP123 = TESTPOINT: TESTPOINT CIR 20 SMD; Chkd/date: SHREESHAIL/171006; Crtd /date: MAZHAR/171006; Custom_Duty: NA; Customs_HS_Code: NA; Distributor_name: NA; Distributor_part_number: NA; Footprint Path: Y:\MIS_DATABASE\Library\ALTIUM_TOOL\PCB_FOOTPRINTS\Altium_Footprint_Lib.PcbLib; Height: NA; Library Path: Y:\MIS_DATABASE\Library\ALTIUM_TOOL\SCHEMATICS_PARTS\MS_DISCRETE_Library.schlib; MECHANICAL 3D STEP FILE: NA; Mfr_name: LOCAL; Mistral Part No: NA; Package: SMD; Project: BT MODULE_CSRBC04; RoHS: NA; Temperature: NA; Tolerance: NA; Voltage: NA; Wattage: NA; Weight: NA; Datasheet: NA
C510-C516 = CAP: CAP CERAMIC 0.1uF 16V 10% X5R 0201; Alt_Mfr_name: YAGEO AMERICA; Alt_Mfr_part_number: CC0402KRX5R8BB104; Chkd/date: MANIRAJA/230118; Crtd /date: MANIRAJA/230118; Custom_Duty: 15%; Customs_HS_Code: 85322990; Distributor_name: DIGIKEY; Distributor_part_number: 490-14305-1-ND; Footprint Path: Y:\MIS_DATABASE\Library\ALTIUM_TOOL\PCB_FOOTPRINTS\Altium_Footprint_Lib.PcbLib; Height: 0.33MM; Library Path: Y:\MIS_DATABASE\Library\ALTIUM_TOOL\SCHEMATICS_PARTS\MS_DISCRETE_Library.schlib; Mfr_name: MURATA; Mfr_part_number: GRM033R61C104KE14D; Mistral Part No: 120009030072-R; Package: 0201; Part_type: CAPACITORS\CERAMIC; Project: TI_MAXIE_CPB; RoHS: RoHS; Temperature: -55°C+85°C; Tolerance: 10%; Voltage: 16V; Wattage: NA; Weight: 0.33mg; Datasheet: Y:\MIS_DATABASE\DATASHEETS\CAPACITORS\GRM033R61C104KE14.PDF
R224-R226 R229-R232 = RESISTOR: RES 0E 1/20W 5% 0201; Chkd/date: NAVEED/301214; Crtd /date: MUDDU/120710; Custom_Duty: 15%; Customs_HS_Code: 85332119; Distributor_name: DIGIKEY; Distributor_part_number: 311-0.0NCT-ND; Footprint Path: Y:\MIS_DATABASE\Library\ALTIUM_TOOL\PCB_FOOTPRINTS\Altium_Footprint_Lib.PcbLib; Height: 0.26MM; Library Path: Y:\MIS_DATABASE\Library\ALTIUM_TOOL\SCHEMATICS_PARTS\MS_DISCRETE_Library.schlib; Mfr_name: YAGEO AMERICA; Mfr_part_number: RC0201JR-070RL; Mistral Part No: 110010070067-R; Package: 0201; Part_type: RESISTORS\FIXED; Project: PB_BUGBASE; RoHS: RoHS; Temperature: -55°C+125°C; Tolerance: 5%; Voltage: NA; Wattage: 1/20W; Weight: 0.17mg; Datasheet: Y:\MIS_DATABASE\DATASHEETS\RESISTORS\RCXXXXL-SER_MAR18.PDF
R525 R544 R580 R598 = RESISTOR: RES 0E 1/16W JUMPER 0402; Chkd/date: VASANTHA/201216; Crtd /date: MUDDU/190810; Custom_Duty: 15%; Customs_HS_Code: 85332119; Distributor_name: DIGIKEY; Distributor_part_number: 541-0.0JCT-ND; Footprint Path: Y:\MIS_DATABASE\Library\ALTIUM_TOOL\PCB_FOOTPRINTS\Altium_Footprint_Lib.PcbLib; Height: 0.40MM; Library Path: Y:\MIS_DATABASE\Library\ALTIUM_TOOL\SCHEMATICS_PARTS\MS_DISCRETE_Library.schlib; Mfr_name: VISHAY; Mfr_part_number: CRCW04020000Z0ED; Mistral Part No: 110010080019-R; Package: 0402; Part_type: RESISTORS\FIXED; Project: PB_BUGBASE; RoHS: RoHS; Temperature: -55°C+155°C; Tolerance: NA; Voltage: NA; Wattage: 1/16W; Weight: 0.65mg; Datasheet: Y:\MIS_DATABASE\DATASHEETS\RESISTORS\CRCW0603.PDF
R685 R688 R691 R765-R770 R789 = RESISTOR: RES 10K 1/20W 5% 0201; Chkd/date: MANIRAJA/050517; Crtd /date: MANIRAJA/050517; Custom_Duty: 15%; Customs_HS_Code: 85332119; Distributor_name: DIGIKEY; Distributor_part_number: 311-10KNCT-ND; Footprint Path: Y:\MIS_DATABASE\Library\ALTIUM_TOOL\PCB_FOOTPRINTS\Altium_Footprint_Lib.PcbLib; Height: 0.26MM; Library Path: Y:\MIS_DATABASE\Library\ALTIUM_TOOL\SCHEMATICS_PARTS\MS_DISCRETE_Library.schlib; Mfr_name: YAGEO AMERICA; Mfr_part_number: RC0201JR-0710KL; Mistral Part No: 110010070051-R; Package: 0201; Part_type: RESISTORS\FIXED; Project: GOLDEN-I LITE; RoHS: RoHS; Temperature: -55°C+125°C; Tolerance: 5%; Voltage: NA; Wattage: 1/20W; Weight: 0.17mg; Datasheet: Y:\MIS_DATABASE\DATASHEETS\RESISTORS\RCXXXXL-SER_MAR18.PDF
R686 R687 R689 R690 = RESISTOR: RES 4.7K 1/20W 5% 0201; Chkd/date: MANIRAJA/200921; Crtd /date: ALVY/200921; Custom_Duty: 15%; Customs_HS_Code: 85332119; Distributor_name: DIGIKEY; Distributor_part_number: 311-4.7KNCT-ND; Footprint Path: Y:\MIS_DATABASE\Library\ALTIUM_TOOL\PCB_FOOTPRINTS\Altium_Footprint_Lib.PcbLib; Height: 0.26MM; Library Path: Y:\MIS_DATABASE\Library\ALTIUM_TOOL\SCHEMATICS_PARTS\MS_DISCRETE_Library.schlib; Mfr_name: YAGEO AMERICA; Mfr_part_number: RC0201JR-074K7L; Mistral Part No: 110021090007-R; Package: 0201; Part_type: RESISTORS\FIXED; Project: TI_AM62x SKEVM_BRD; RoHS: RoHS; Temperature: -55°C+125°C; Tolerance: 5%; Voltage: NA; Wattage: 1/20W; Weight: 0.17mg; Datasheet: Y:\MIS_DATABASE\DATASHEETS\RESISTORS\RCXXXXL-SER_MAR18.PDF
R692-R694 = RESISTOR: RES 1K 1/10W 5% 0402; Chkd/date: VASANTHA/201216; Crtd /date: MAZHAR/230805; Custom_Duty: 15%; Customs_HS_Code: 85332119; Distributor_name: DIGIKEY; Distributor_part_number: P1.0KJCT-ND; Footprint Path: Y:\MIS_DATABASE\Library\ALTIUM_TOOL\PCB_FOOTPRINTS\Altium_Footprint_Lib.PcbLib; Height: 0.40MM; Library Path: Y:\MIS_DATABASE\Library\ALTIUM_TOOL\SCHEMATICS_PARTS\MS_DISCRETE_Library.schlib; Mfr_name: PANASONIC-ECG; Mfr_part_number: ERJ-2GEJ102X; Mistral Part No: 110009030400-R; Package: 0402; Part_type: RESISTORS\FIXED; Project: HSE; RoHS: RoHS; Temperature: -55°C+155°C; Tolerance: 5%; Voltage: NA; Wattage: 1/10W; Weight: 0.8mg; Datasheet: Y:\MIS_DATABASE\DATASHEETS\RESISTORS\PAN-ERJSER_NOV17.PDF
U106 U107 = TCA9517DGKR_VSSOP8: IC 2-CHANNEL BI-DIR LEVEL-SHIFTING I2C BUS REPEATER SOIC8; Chkd/date: MANIRAJA/171121; Crtd /date: ALVY/161121; Custom_Duty: 15%; Customs_HS_Code: 85423100; Distributor_name: DIGIKEY; Distributor_part_number: 296-39221-1-ND; Footprint Path: Y:\MIS_DATABASE\Library\ALTIUM_TOOL\PCB_FOOTPRINTS\Altium_Footprint_Lib.PcbLib; Height: 1.75MM; Library Path: Y:\MIS_DATABASE\Library\ALTIUM_TOOL\SCHEMATICS_PARTS\MS_MISCINTERFACE_Library.schlib; Mfr_name: TEXAS INSTRUMENTS; Mistral Part No: 141021110017-R; Package: SOIC8; Part_type: ICS\INTERFACE\LEVEL TRANSLATOR; Project: EXCITER MULTI-CH RX UNIT; RoHS: RoHS; Temperature: -40°C+85°C; Tolerance: NA; Voltage: NA; Wattage: NA; Weight: 540mg; Datasheet: Y:\MIS_DATABASE\DATASHEETS\ICS\INTERFACE\TCA9517.PDF
U108 = 74HC7014X_SOIC14: IC HEX BUFFER AND DRIVER WITH OPEN DRAIN OUTPUT TVSOP14; Chkd/date: ALVY/070422; Crtd /date: TAMILARASU/070422; Custom_Duty: 15%; Customs_HS_Code: 85423100; Distributor_name: DIGIKEY; Distributor_part_number: 296-8440-1-ND; Footprint Path: Y:\MIS_DATABASE\Library\ALTIUM_TOOL\PCB_FOOTPRINTS\Altium_Footprint_Lib.PcbLib; Height: 1.20MM; Library Path: Y:\MIS_DATABASE\Library\ALTIUM_TOOL\SCHEMATICS_PARTS\MS_COMBINATIONAL_Library.schlib; Mfr_name: TEXAS INSTRUMENTS; Mistral Part No: 141022040005-R; Package: TVSOP14; Part_type: ICS\DIGITAL\COMBINATIONAL; Project: TI_AM62x_SKEVM_BRD; RoHS: RoHS; Temperature: -40°C+125°C; Tolerance: NA; Voltage: NA; Wattage: NA; Weight: 41.8mg; Datasheet: Y:\MIS_DATABASE\DATASHEETS\ICS\DIGITAL\COMBINATIONAL\SN74LVC07A.PDF
U109 = TXS0102DQX_SON8: IC 2-BIT BI-DIR VOLTAGE-LEVEL TRANSLATOR FOR OPEN-DRAIN AND PUSH-PULL X2SON8; Chkd/date: MANIRAJA/010719; Crtd /date: CHAITHANYA230512; Custom_Duty: 15%; Customs_HS_Code: 85423100; Distributor_name: DIGIKEY; Distributor_part_number: 296-28368-1-ND; Footprint Path: Y:\MIS_DATABASE\Library\ALTIUM_TOOL\PCB_FOOTPRINTS\Altium_Footprint_Lib.PcbLib; Height: 0.40MM; Library Path: Y:\MIS_DATABASE\Library\ALTIUM_TOOL\SCHEMATICS_PARTS\MS_MISCINTERFACE_Library.schlib; Mfr_name: TEXAS INSTRUMENTS; Mistral Part No: 141012050010-R; Package: X2SON8; Part_type: ICS\INTERFACE\LEVEL TRANSLATOR; Project: GEN_3-8_DB; RoHS: RoHS; Temperature: -40°C+85°C; Tolerance: NA; Voltage: NA; Wattage: NA; Weight: 1.2mg; Datasheet: Y:\MIS_DATABASE\DATASHEETS\ICS\INTERFACE\TXS0102-SER.PDF

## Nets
DGND: C41.2 C48.2 C49.2 C88.2 C89.2 C90.2 C220.2 C221.2 C222.2 C243.2 C245.2 C246.2 C263.2 C270.2 C275.2 C281.2 C283.2 C284.2 C285.2 C287.2 C288.2 C289.2 C290.2 C296.2 C297.2 C298.2 C299.2 C300.2 C510.1 C511.1 C512.1 C513.1 C514.2 C515.2 C516.2 C527.1 C547.2 C548.2 R685.1 R688.1 R691.1 U106.4(GND) U107.4(GND) U108.7(GND) U109.3(A2) U109.4(GND) U109.6(B2) ; also on sheet 12 13 14 15 16 17 18 19 20 21 22 23 24 25 26 27 28 29 30 31 32 33 34 35 36 37 38 39 40 41 42 43 44 45
VCC3V3_TA: C513.2 C516.1 R693.2 R694.2 U107.8(VCCB) U109.8(VCCB) ; also on sheet 28 29
VCC3V3_XDS: C510.2 C512.2 C514.1 C515.1 R686.1 R687.1 R689.1 R690.1 R692.2 R765.1 R766.1 R767.1 R768.1 R769.1 R770.1 R789.1 U106.1(VCCA) U107.1(VCCA) U108.14(VCC) U109.1(VCCA) ; also on sheet 30 31
VCC_3V3_MAIN: FL18.1 ; also on sheet 14 15 28
VCC_3V3_SYS: C511.2 U106.8(VCCB) ; also on sheet 12 14 15 16 20 21 22 24 25 26 27 28 29 31 32 33 34 35 36 37 38 39 40 41 42 43 44 45
VDD_CORE: FL4.1 FL7.1 ; also on sheet 15 16 17 18
VDDA_1V8: FL3.1 FL5.1 FL6.1 FL9.1 FL13.1 FL16.1 FL19.1 ; also on sheet 15 17 18
VDDA_1V8_CSIRX: C41.1 C243.1 C270.1 FL3.2 ; also on sheet 17
VDDA_1V8_MCU: C88.1 C89.1 C90.1 FL9.2 ; also on sheet 17
VDDA_1V8_OLDI: C284.1 C285.1 C290.1 FL5.2 ; also on sheet 17
VDDA_1V8_USB: C287.1 C297.1 C298.1 FL6.2 ; also on sheet 17
VDDA_CORE_CSI: C48.1 C275.1 C281.1 FL4.2 ; also on sheet 17
VDDA_CORE_USB: C49.1 C283.1 C289.1 FL7.2 ; also on sheet 17
VDDA_PLL0: C245.1 C246.1 C288.1 FL16.2 ; also on sheet 17
VDDA_PLL1: C220.1 C221.1 C222.1 FL13.2 ; also on sheet 17
VDDA_PLL2: C296.1 C299.1 C300.1 FL19.2 ; also on sheet 17
VDDSHV_SDIO: FL14.1 ; also on sheet 22
BOOTMODE_I2C_EN: R688.2 R694.1 U107.5(EN)
BOOTMODE_I2C_SCL: R598.2 ; also on sheet 28 29
BOOTMODE_I2C_SDA: R580.2 ; also on sheet 28 29
BOOTMODE_XDS_I2C_SCL: R690.2 U107.2(SCLA) ; also on sheet 30
BOOTMODE_XDS_I2C_SDA: R689.2 U107.3(SDAA) ; also on sheet 30
CAN_IO_3V3: C547.1 C548.1 FL18.2 TP123.1(TP) ; also on sheet 17 33 36
SOC_I2C1_SCL: R544.2 ; also on sheet 16 24 28 41 42 43 44
SOC_I2C1_SDA: R525.2 ; also on sheet 16 24 28 41 42 43 44
SoC_I2C1_XDS_SCL: R686.2 U106.2(SCLA) ; also on sheet 30
SoC_I2C1_XDS_SDA: R687.2 U106.3(SDAA) ; also on sheet 30
SoC_VDDSHV5_SDIO: C263.1 C527.2 FL14.2 ; also on sheet 17
TEST_GPIO1: R225.2 ; also on sheet 28 45
TEST_GPIO1_XDS: R765.2 U108.1(1A) ; also on sheet 30
TEST_GPIO2: R231.2 ; also on sheet 28
TEST_GPIO2_XDS: R789.2 U109.2(A1) ; also on sheet 30
TEST_GPIO3: R226.2 ; also on sheet 28 29
TEST_GPIO3_XDS: R766.2 U108.3(2A) ; also on sheet 30
TEST_GPIO4: R232.2 ; also on sheet 28 29
TEST_GPIO4_XDS: R767.2 U108.5(3A) ; also on sheet 30
TEST_PORZn: R224.2 ; also on sheet 28 44
TEST_PORZn_XDS: R768.2 U108.9(4A) ; also on sheet 30
TEST_POWERDOWN: R229.2 ; also on sheet 15 28
TEST_POWERDOWN_XDS: R770.2 U108.13(6A) ; also on sheet 30
TEST_WARMRESETn: R230.2 ; also on sheet 28 45
TEST_WARMRESETn_XDS: R769.2 U108.11(5A) ; also on sheet 30
XDS_I2C1_EN: R685.2 R693.1 U106.5(EN)
N20501313: R231.1 U109.7(B1)
N20503848: R691.2 R692.1 U109.5(OE)
N20547674: R225.1 U108.2(1Y)
N20547852: R226.1 U108.4(2Y)
N20548002: R232.1 U108.6(3Y)
N20548130: R224.1 U108.8(4Y)
N20548208: R230.1 U108.10(5Y)
N20548250: R229.1 U108.12(6Y)
N20610314: R544.1 U106.7(SCLB)
N20610315: R525.1 U106.6(SDAB)
N20611580: R598.1 U107.7(SCLB)
N20611582: R580.1 U107.6(SDAB)

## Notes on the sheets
sheet 1
- SOC POWER SUPPLIES - DECAPS 2
- PERIPHERALS - 1.8V ANALOG SUPPLIES
- PERIPHERALS - CORE SUPPLIES
- CAN_IO_3V3
- C
- 3.3V/1.8V MMC1 SUPPLY
- C
- D-Note:
  Common SoC LVCMOS IO Interface Guidelines:
  1. Most of the SoC IOs are not fail-safe. No input should be applied before processor supply ramps.
  2. SoC LVCMOS inputs have minimum slew rate requirements specified.
  3. SoC IO buffers are off during Reset. A pull pull is required near to the attached device input
  being driven by the SOC IOs (input does not float).
  4. Any SoC IO that has a trace connected and not being actively driven needs a parallel pull. When
  adding a pull is not feasible, ensure the trace is routed away from noisy signals.
  5. When the IOs are unused, leave the IOs unconnected and the PADCONFIG setting in the default state.
sheet 2
- LINKS TO KEY COLLATERALS
- Hardware Design Guide:
- https://www.ti.com/lit/an/sprad05b/sprad05b.pdf
- Schematic Design checklist, General guidelines and Review Checklist for AM62x Processor Family:
- https://www.ti.com/lit/pdf/sprado3
- PMIC Power Solutions Application Note:
- https://www.ti.com/lit/an/slvafd0b/slvafd0b.pdf
- DDR Board Design and Layout Guidelines:
- https://www.ti.com/lit/an/sprad06/sprad06.pdf
- SKs (Starter Kits) for Reference:
- SK-AM62B, SK-AM62B-P1, SK-AM62-LP, SK-AM62-SIP, SK-AM62A-LP, SK-AM62P-LP
- Schematic Design guidelines combined for Sitara processor families :
- https://www.ti.com/lit/pdf/sprad21
- LINKS TO KEY FAQs
- https://e2e.ti.com/support/processors-group/processors/f/processors-forum/1183910/faq-am625-custom-board-hardware-design-collaterals-to-get-started
- https://e2e.ti.com/support/processors-group/processors/f/processors-forum/1184006/faq-am623-custom-board-hardware-design-collaterals-to-get-started
- https://e2e.ti.com/support/processors-group/processors/f/processors-forum/1285107/faq-am64x-am62x-am62ax-am62px-custom-board-hardware-design---
  collaterals-for-reference-during-schematic-design-and-schematics-review
- https://e2e.ti.com/support/processors-group/processors/f/processors-forum/1280721/faq-am625-am623-am625sip-am625-q1-am620-q1-custom-board-hardware-
  design---faqs-related-to-processor-collaterals-functioning-peripherals-interface-and-starter-kit
- https://e2e.ti.com/support/processors-group/processors/f/processors-forum/1332316/faq-am625-am623-custom-board-hardware-design---design-and-
  review-notes-for-reuse-of-sk-am62b-p1-schematics
- https://e2e.ti.com/support/processors-group/processors/f/processors-forum/1596731/faq-am625-am623-am620-q1-am625-q1-am625sip---collaterals-for-reference-during-
  different-phases-of-custom-board-design-self-review-and-bring-up
- https://e2e.ti.com/support/processors-group/processors/f/processors-forum/1454755/faq-am625-am623-am62aam62p-am62d-q1-am64x-am243x-design-recommendations-
  custom-board-hardware-design---queries-related-to-soc-data-sheet-pin-attributes
- https://e2e.ti.com/support/processors-group/processors/f/processors-forum/1457736/faq-am625-am623-am62a-am62p-am62d-q1-am64x-am243x-design-recommendations-
  custom-board-hardware-design---schematics-review-checklists
- https://e2e.ti.com/support/processors-group/processors/f/processors-forum/1318441/faq-am625-am623-am62adesign-recommendations-commonly-observed-errors-during-
  custom-board-hardware-design-sk-schematics-updates-for-design-update-note
- https://e2e.ti.com/support/processors-group/processors/f/processors-forum/1455706/faq-am625-am623-am620-q1-am625-q1-am625sip-design-recommendations-custom-
  board-hardware-design---custom-board-schematics-self-review
- https://e2e.ti.com/support/processors-group/processors/f/processors-forum/1455682/faq-am625-am623-am620-q1-am62l-am62a-am62p-am62d-q1-am64x-am243x-design-
  recommendations-custom-board-hardware-design---list-of-errors-observed-during-customer-schematics-review
sheet 3
- SOC I2C BUS BUFFER
- BOOTMODE_I2C_TA BUFFER
- V
- V
- ISOLATION BUFFERS FOR TA SIGNALS
- D-Note:
  Pull-ups (R587, R517, R568, R586, R566, R585 & R567) referenced to
  VCC3V3_TA are added near to the  test automation header
sheet 4
- AM625 / AM623 Starter Kit SK (EVM) WITH TPS6521904 PMIC
- TABLE OF CONTENTS
- Revision Number
- PAGE
- CONTENTS
- PAGE
- CONTENTS
- REV
- B
- 01
- TABLE OF CONTENTS
- 25
- CPSW3G RGMII_2 ETHERNET PHY
- VER
- 0.15
- 02
- REVISION HISTORY
- 26
- SOC MAC INTRFACE, SOC AND ETHERNET PHYs CLOCK BUFFER, LED DRIVER
- 03
- LINKS TO KEY COLLATERALS AND FAQs
- 27
- TEST AUTOMATION
- 04
- BLOCK DIAGRAM FOR AM625 / AM623 STARTER KIT SK (EVM)
- 28
- BOOT MODE CONFIGURATION BUFFERS, RESISTOR DIVIDERS & DIP SWITCHES
- 05
- BLOCK DIAGRAM XDS110 DEBUGGER
- 29
- XDS110 DEBUGGER
- 06
- POWER-UP SEQUENCE AND POWER ARCHITECTURE BLOCK DIAGRAM
- 30
- AUTOMATION SIGNALS BUFFER
- 07
- POWER SEQUENCE
- 31
- SOC JTAG INTERFACE AND JTAG BUFFERS
- 08
- I2C TREE
- 32
- JTAG 20 PIN cTI CONNECTOR AND BUFFERS
- 09
- GPIO MAPPING TABLE
- 33
- FT4232 UART TO USB BRIDGE
- 10
- USB TYPE-C PD CONTROLLER AND POWER SUPPLY
- 34
- SOC LFOSC0 AND SOC BOOTMODE INPUT PINS, PRU HEADER
- 11
- PERIPHERAL POWER SUPPLIES-1
- 35
- USER EXPANSION CONNECTOR
- 12
- PERIPHERAL POWER SUPPLIES-2
- 36
- SOC-MCU DOMAIN IO, OSC0 AND SOC-MCU IO HEADER
- 13
- SOC POWER SUPPLIES - PMIC BASED WITH SOC CURRENT MEASUREMENT SHUNTS
- 37
- USB0 TYPE-C DRP
- 14
- SOC SUPPLY RAILS CURRENT MEASUREMENT DEVICES
- 38
- SOC USB INTERFACE, USB1 TYPE-A CONNECTOR, VBUS DIVIDER & POWER SWITCH
- 15
- SOC POWER SUPPLIES, SUPPLY RAILS AND SOC GROUND VSS
- 39
- SOC OLDI INTERFACE, LCD CONNECTOR AND SOC UART1 FET SWITCH & BUFFER
- 16
- SOC POWER SUPPLIES - DECAPS 1
- 40
- SOC CSI INTERFACE AND CAMERA CONNECTOR
- 17
- SOC POWER SUPPLIES - DECAPS 2
- 41
- IO EXPANDER AND MCASP1 FET SWITCH & BUFFER
- 18
- SOC DDRSS AND DDR4 MEMORY DEVICE INTERFACE
- 42
- AUDIO CODEC
- 19
- M.2 INTERFACE AND CONNECTOR
- 43
- SOC DPI INTERFACE, DPI TO HDMI TRANSMITTER INTERFACE
- 20
- SOC MMC0.2 INTERFACE AND eMMC FLASH + RESET
- 44
- SOC RESETs AND IOs, AND EXTERNAL LVCMOS CLOCK (OSCILLATOR)
- 21
- SD CARD - LOAD SWITCH, LOAD SWITCH RESET LOGIC AND DATA INTERFACE
- 45
- SOC PUSH BUTTON RESET INPUTS, DEBOUNCE LOGIC FOR RC RESET
- 22
- SOC OSPI/QSPI INTERFACE AND OSPI FLASH
- 46
- ASSEMBLY NOTES AND MOUNTING HARDWARE
- 23
- BOARD ID EEPROM & DIGITAL TEMPERATURE SENSORS
- 24
- CPSW3G RGMII_1 ETHERNET PHY
- D-Note:
- SK/EVM is an evaluation board or platform. The SK/EVM is not a reference design. In some cases, the EVM implementation may deviate from the optimum
  solution to provide a better customer experience or provide flexibility for customers to be able to validate the SoC functionality. TI expects and
  recommends customers to carefully review and follow all requirements defined in the datasheet, silicon errata and TRM when designing their custom
  board. The information found in the datasheet should always take precedence over the SK/EVM implementation.
- R-Note:
- * Verify the DNI components configuration with respect to the SK schematics (use PDF) after completion of board design before board assembly.
  * A standard 5% tolerance resistor can be used for most of the series and parallel pull resistors.
  * Be sure to read through all the D-Notes (Design notes), R-Notes (Review notes) and CAD notes during board design and before start of board
  build.  (Refer FAQs listed for additional details).
- Indicates circuit level change
- C
- Indicates that the value of the component has been updated.
- V
sheet 5
- REVISION HISTORY
- VER #
- DATE
- DESCRIPTION OF CHANGES
- AUTHOR
- REVIEWED BY
- APPROVED BY
- 0.01
- 20 Jun 2025
- - Drafted from PROC142A1 Schematics
  - Added optional clock path for EXP_CLKOUT0 signal on the Expansion header to support DANTE
- Mistral Design Team
- Pandiyarajan
- 26 Jun 2025
- Updated TIVA and XDS section as per TI requirement
- Mistral Design Team
- Pandiyarajan
- 0.02
- 0.03
- 14 July 2025
- Implemented the review comments shared by TI
- Mistral Design Team
- Pandiyarajan
- 0.04
- 21 July 2025
- - Replaced U13 with a dual-channel load switch
  - Changed the implementation of AUDIO_EXT_REFCLK1
- Mistral Design Team
- Pandiyarajan
- 0.05
- 12 Aug 2025
- - Added U113 regulator and corresponding components for VDD_CANUART implementation
  - Implemented partial IO support for FT4232 UART
- Mistral Design Team
- Pandiyarajan
- 0.06
- 22 Sept 2025
- - TP124 has been added to U12.B7 pin of the SoC
  - D16 and D17 ESD diodes have been added to J26 and J25 headers respectively
  - R785, R784 and R786 pulldown resistors have been added to AUDIO_EXT_REFCLK1_R, EXP_CLKOUT0
  and AUDIO_EXT_REFCLK1 signals respectively
- Mistral Design Team
- Pandiyarajan
- 0.07
- 07 Oct 2025
- - Changed the supply from VCC3V3_EXP to VCC_3V3_SYS on U111 & R717
  - Moved U112 and the corresponding components to the User Expansion Connector section & added the
  respective D-Notes
- Mistral Design Team
- Pandiyarajan
- 0.08
- 03 Nov 2025
- - R96 has been changed from 10k to 47k
  - VCCB of U106 has been changed from VCC3V3_TA to VCC_3V3_SYS
  - Pull-ups R787 & R788 have been added in the FT4232 UART buffers section
  - Pull-up resistor R789 has been added on TEST_GPIO2_XDS signal
- Mistral Design Team
- Pandiyarajan
- 0.09
- 04 Nov 2025
- - U34 part number has been changed to TPS2051BD and the corresponding circuit has been updated
  - U114 and the corresponding circuit have been added for ESD protection of USB data lines
  - Y4 part number has been changed to ABM11W-25.0000MHZ-8-D1X-T3; C303 and C305 have been
  updated to 13pF
- Mistral Design Team
- Pandiyarajan
- 0.10
- 11 Nov 2025
- Implemented the review comments shared by TI
- Mistral Design Team
- Pandiyarajan
- 0.11
- 09 Jan 2026
- Mounted R6 (The production revision of Wi-Fi+BT module "M.2-CC3351" requires R6 resistor
  as confirmed by TI)
- Mistral Design Team
- Pandiyarajan
- Below components have been updated based on TI review comments checklist:
  1. Value of C232 is changed from 22uF to 4.7uF
  2. C491, C534, C535, C536, C537 have been changed from 10pF to 47pF
  3. R613, R743, R744, R746, R747 have been changed from 620E to 62E
  4. Mounted R363
  5. Added D-Notes
- 23 March 2026
- Pandiyarajan
- 0.12
- Mistral Design Team
- - Added D-notes
  - Added blocks to indicate value/circuit changes form rev A to B
- Pandiyarajan
- 0.13
- 31 March 2026
- Mistral Design Team
- Below components have been updated based on TI review comments checklist:
  1. Tolerance of R502, R495, R461, R6, R305, R563, R560, R556, R552, R260, R259, R258, R255,
  R694, R693 and R400 resistors has been changed from 1% to 5%
  2. Value of R304 has been changed from 47K to 10K
  3. Value of R330 has been changed from 1.5K to 2.2K
  4. Value of R614 & R617 has been changed from 1K to 470E
  5. Value of R88 & R188 has been changed from 220E to 470E
  6. Added and updated D-Notes
- 0.14
- 14 April 2026
- Mistral Design Team
- Pandiyarajan
- 0.15
- 23 April 2026
- Updated D-Notes
- Mistral Design Team
- Pandiyarajan
sheet 6
- BLOCK DIAGRAM
sheet 7
- BLOCK DIAGRAM_XDS110
- D-Note:
- Please follow SK-AM62P-LP  implementations for latest updates on XDS110
sheet 8
- POWER BLOCK DIAGRAM
sheet 9
- POWER SEQUENCE
sheet 10
- I2C TREE
- R-Note:
- Refer to the following section of the data sheet:
  Timing and Switching Characteristics - I2C - Exceptions
- R-Note:
- Add -
  Indicates
  Address
- R-Note:
- For emulated open-drain output type LVCMOS I2C interfaces (I2C0,
  I2C1, I2C2, I2C3), pull-up resistors are recommended when the IOs are
  configured for I2C interface. The IOs associated with these
  I2C interfaces are not compliant to the fall time requirements
  defined in the I2C specification. A series resistor is used to
  control the fall time. Location of the pull-up is not critical.
  The recommendation to connect the pull-ups with the shortest
  possible stub.
- R-Note:
- For I2C interfaces with open-drain output type buffer
  (MCU_I2C0 and WKUP_I2C0), an external pull-up is
  recommended irrespective of peripheral usage and IO configuration.
  An RC to limit the slew rate (C placed near to SOC pin) is recommended.
  Refer to the Pin Connectivity Requirements section of the SoC data sheet.
sheet 11
- GPIO MAPPING TABLE
